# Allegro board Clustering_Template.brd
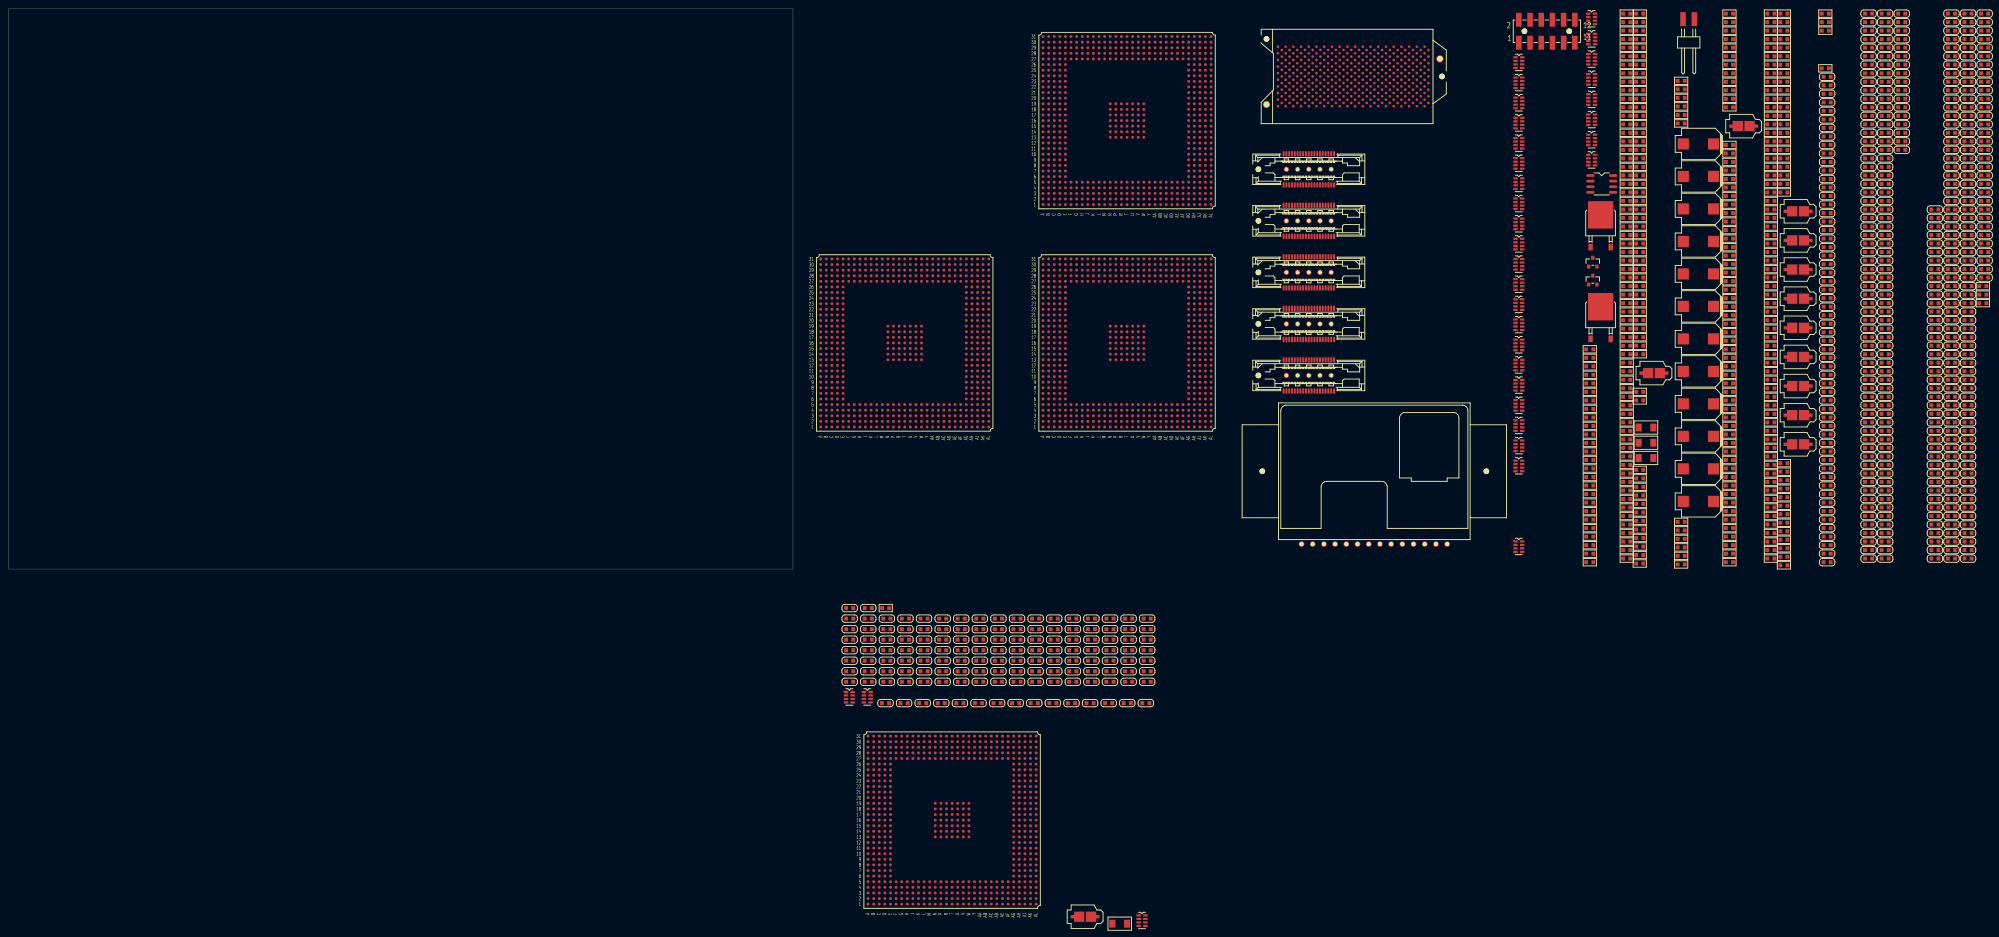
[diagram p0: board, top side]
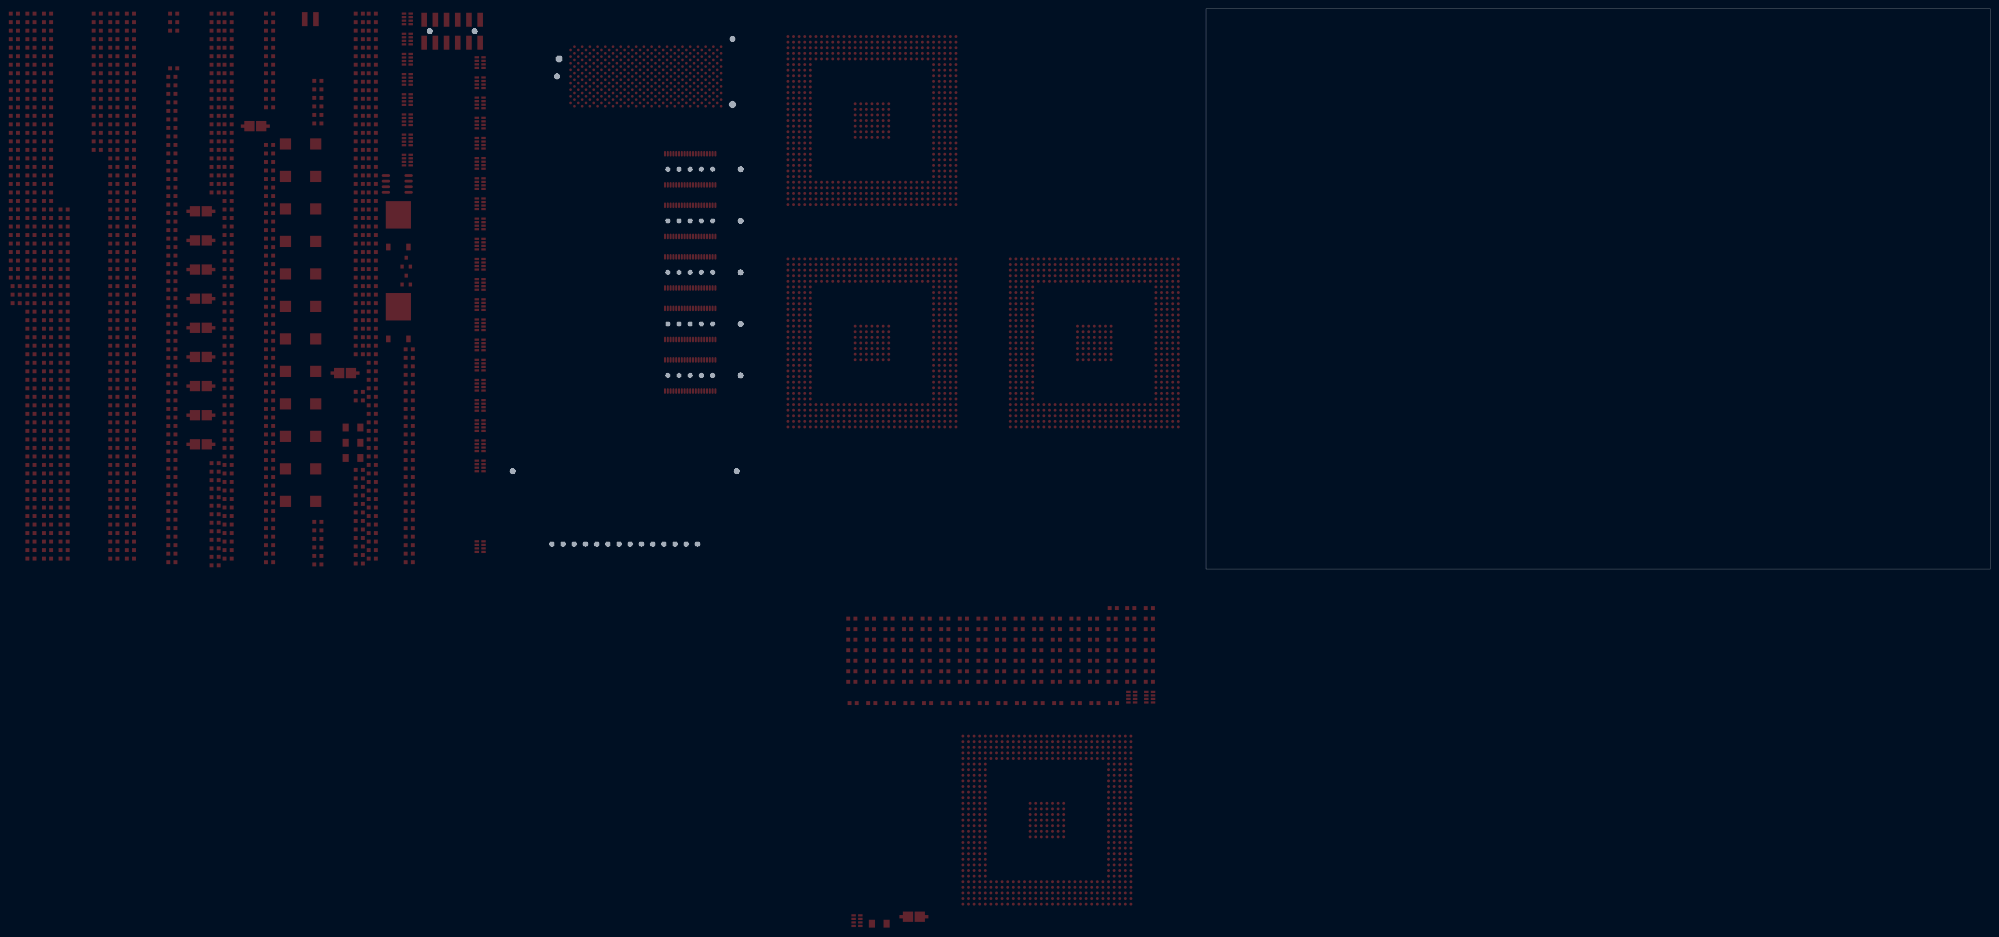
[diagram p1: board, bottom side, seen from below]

Outline 177.8 x 127 mm; copper layers: TOP, INNER1, INNER2, INNER3, INNER4, BOTTOM. Coordinates in mm from the lower left corner of the outline.
Outline path: 0,127 0,0 177.8,0 177.8,127 0,127

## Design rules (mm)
constraint set DEFAULT: min track width 0.114
net group PWR_NET: nets 3.3V GND

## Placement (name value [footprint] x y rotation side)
C1  470PF_50V  [RC0603_1]  399.53 25.53 0 top
C2  470PF_50V  [RC0603_1]  399.53 27.46 0 top
C3  470PF_50V  [RC0603_1]  399.53 29.39 0 top
C4  470PF_50V  [RC0603_1]  399.53 31.32 0 top
C5  470PF_50V  [RC0603_1]  399.53 33.25 0 top
C6  470PF_50V  [RC0603_1]  399.53 35.18 0 top
C7  470PF_50V  [RC0603_1]  399.53 37.11 0 top
C8  470PF_50V  [RC0603_1]  399.53 39.04 0 top
C9  470PF_50V  [RC0603_1]  399.53 40.97 0 top
C10  470PF_50V  [RC0603_1]  399.53 42.9 0 top
C11  470PF_50V  [RC0603_1]  399.53 44.83 0 top
C12  470PF_50V  [RC0603_1]  399.53 46.76 0 top
C13  470PF_50V  [RC0603_1]  399.53 48.69 0 top
C14  470PF_50V  [RC0603_1]  399.53 50.62 0 top
C15  470PF_50V  [RC0603_1]  399.53 52.55 0 top
C16  470PF_50V  [RC0603_1]  399.53 54.48 0 top
C17  470PF_50V  [RC0603_1]  399.53 56.41 0 top
C18  470PF_50V  [RC0603_1]  399.53 58.34 0 top
C19  470PF_50V  [RC0603_1]  399.53 60.27 0 top
C20  470PF_50V  [RC0603_1]  399.53 62.2 0 top
C21  470PF_50V  [RC0603_1]  399.53 64.14 0 top
C22  470PF_50V  [RC0603_1]  399.53 66.07 0 top
C23  470PF_50V  [RC0603_1]  399.53 68 0 top
C24  470PF_50V  [RC0603_1]  399.53 69.93 0 top
C25  470PF_50V  [RC0603_1]  399.53 71.86 0 top
C26  470PF_50V  [RC0603_1]  399.53 73.79 0 top
C27  470PF_50V  [RC0603_1]  399.53 75.72 0 top
C28  470PF_50V  [RC0603_1]  399.53 77.65 0 top
C29  470PF_50V  [RC0603_1]  399.53 79.58 0 top
C30  470PF_50V  [RC0603_1]  399.53 81.51 0 top
C31  470PF_50V  [RC0603_1]  399.53 83.44 0 top
C32  470PF_50V  [RC0603_1]  399.53 85.37 0 top
C33  470PF_50V  [RC0603_1]  399.53 87.3 0 top
C34  470PF_50V  [RC0603_1]  399.53 89.23 0 top
C35  470PF_50V  [RC0603_1]  399.53 91.16 0 top
C36  470PF_50V  [RC0603_1]  399.53 93.09 0 top
C37  470PF_50V  [RC0603_1]  399.53 95.02 0 top
C38  470PF_50V  [RC0603_1]  399.53 96.95 0 top
C39  470PF_50V  [RC0603_1]  399.53 98.88 0 top
C40  470PF_50V  [RC0603_1]  399.53 100.81 0 top
C41  470PF_50V  [RC0603_1]  399.53 102.74 0 top
C42  470PF_50V  [RC0603_1]  399.53 104.67 0 top
C43  470PF_50V  [RC0603_1]  399.53 106.6 0 top
C44  470PF_50V  [RC0603_1]  399.53 108.53 0 top
C45  470PF_50V  [RC0603_1]  399.53 110.46 0 top
C46  470PF_50V  [RC0603_1]  399.53 112.39 0 top
C47  470PF_50V  [RC0603_1]  399.53 114.33 0 top
C48  470PF_50V  [RC0603_1]  399.53 116.26 0 top
C49  470PF_50V  [RC0603_1]  399.53 118.19 0 top
C50  470PF_50V  [RC0603_1]  399.53 120.12 0 top
C51  470PF_50V  [RC0603_1]  399.53 122.05 0 top
C52  470PF_50V  [RC0603_1]  399.53 123.98 0 top
C53  470PF_50V  [RC0603_1]  399.53 125.91 0 top
C54  470PF_50V  [RC0603_1]  390.13 1.55 0 top
C55  470PF_50V  [RC0603_1]  390.13 3.48 0 top
C56  470PF_50V  [RC0603_1]  390.13 5.41 0 top
C57  470PF_50V  [RC0603_1]  390.13 7.34 0 top
C58  470PF_50V  [RC0603_1]  390.13 9.27 0 top
C59  470PF_50V  [RC0603_1]  390.13 11.2 0 top
C60  470PF_50V  [RC0603_1]  390.13 13.13 0 top
C61  470PF_50V  [RC0603_1]  390.13 15.06 0 top
C62  470PF_50V  [RC0603_1]  390.13 16.99 0 top
C63  470PF_50V  [RC0603_1]  390.13 18.92 0 top
C64  470PF_50V  [RC0603_1]  390.13 20.85 0 top
C65  470PF_50V  [RC0603_1]  390.13 22.78 0 top
C66  470PF_50V  [RC0603_1]  390.13 24.71 0 top
C67  470PF_50V  [RC0603_1]  390.13 26.64 0 top
C68  470PF_50V  [RC0603_1]  390.13 28.57 0 top
C69  470PF_50V  [RC0603_1]  390.13 30.51 0 top
C70  470PF_50V  [RC0603_1]  390.13 32.44 0 top
C71  470PF_50V  [RC0603_1]  390.13 34.37 0 top
C72  470PF_50V  [RC0603_1]  390.13 36.3 0 top
C73  470PF_50V  [RC0603_1]  390.13 38.23 0 top
C74  470PF_50V  [RC0603_1]  390.13 40.16 0 top
C75  470PF_50V  [RC0603_1]  390.13 42.09 0 top
C76  470PF_50V  [RC0603_1]  390.13 44.02 0 top
C77  470PF_50V  [RC0603_1]  390.13 45.95 0 top
C78  470PF_50V  [RC0603_1]  390.13 47.88 0 top
C79  470PF_50V  [RC0603_1]  390.13 49.81 0 top
C80  470PF_50V  [RC0603_1]  390.13 51.74 0 top
C81  470PF_50V  [RC0603_1]  390.13 53.67 0 top
C82  470PF_50V  [RC0603_1]  390.13 55.6 0 top
C83  470PF_50V  [RC0603_1]  390.13 57.53 0 top
C84  470PF_50V  [RC0603_1]  390.13 59.46 0 top
C85  470PF_50V  [RC0603_1]  390.13 61.39 0 top
C86  470PF_50V  [RC0603_1]  390.13 63.32 0 top
C87  470PF_50V  [RC0603_1]  390.13 65.25 0 top
C88  470PF_50V  [RC0603_1]  390.13 67.18 0 top
C89  470PF_50V  [RC0603_1]  390.13 69.11 0 top
C90  470PF_50V  [RC0603_1]  390.13 71.04 0 top
C91  470PF_50V  [RC0603_1]  390.13 72.97 0 top
C92  470PF_50V  [RC0603_1]  390.13 74.9 0 top
C93  470PF_50V  [RC0603_1]  390.13 76.83 0 top
C94  470PF_50V  [RC0603_1]  390.13 78.77 0 top
C95  470PF_50V  [RC0603_1]  390.13 80.7 0 top
C96  470PF_50V  [RC0603_1]  390.13 82.63 0 top
C97  470PF_50V  [RC0603_1]  390.13 84.56 0 top
C98  470PF_50V  [RC0603_1]  390.13 86.49 0 top
C99  470PF_50V  [RC0603_1]  390.13 88.42 0 top
C100  470PF_50V  [RC0603_1]  390.13 90.35 0 top
C101  470PF_50V  [RC0603_1]  390.13 92.28 0 top
C102  470PF_50V  [RC0603_1]  390.13 94.21 0 top
C103  470PF_50V  [RC0603_1]  390.13 96.14 0 top
C104  470PF_50V  [RC0603_1]  411.88 113.51 0 top
C105  470PF_50V  [RC0603_1]  390.13 104.67 0 top
C106  470PF_50V  [RC0603_1]  390.13 106.6 0 top
C107  470PF_50V  [RC0603_1]  390.13 108.53 0 top
C108  470PF_50V  [RC0603_1]  390.13 110.46 0 top
C109  470PF_50V  [RC0603_1]  390.13 112.39 0 top
C110  470PF_50V  [RC0603_1]  390.13 114.33 0 top
C111  470PF_50V  [RC0603_1]  390.13 116.26 0 top
C112  470PF_50V  [RC0603_1]  390.13 118.19 0 top
C113  470PF_50V  [RC0603_1]  390.13 120.12 0 top
C114  470PF_50V  [RC0603_1]  390.13 122.05 0 top
C115  470PF_50V  [RC0603_1]  390.13 123.98 0 top
C116  470PF_50V  [RC0603_1]  390.13 125.91 0 top
C117  470PF_50V  [RC0603_1]  379.19 1.04 0 top
C118  470PF_50V  [RC0603_1]  379.19 2.97 0 top
C119  470PF_50V  [RC0603_1]  379.19 4.9 0 top
C120  0.1UF_16V  [BC0603_P1_1]  198.78 -30.39 0 top
C121  0.1UF_16V  [BC0603_P1_1]  203 -30.39 0 top
C122  0.1UF_16V  [BC0603_P1_1]  207.21 -30.39 0 top
C123  0.1UF_16V  [BC0603_P1_1]  211.43 -30.39 0 top
C124  0.1UF_16V  [BC0603_P1_1]  215.65 -30.39 0 top
C125  0.1UF_16V  [BC0603_P1_1]  219.86 -30.39 0 top
C126  0.1UF_16V  [BC0603_P1_1]  224.08 -30.39 0 top
C127  0.1UF_16V  [BC0603_P1_1]  228.3 -30.39 0 top
C128  0.1UF_16V  [BC0603_P1_1]  232.51 -30.39 0 top
C129  0.1UF_16V  [BC0603_P1_1]  236.73 -30.39 0 top
C130  0.1UF_16V  [BC0603_P1_1]  240.94 -30.39 0 top
C131  0.1UF_16V  [BC0603_P1_1]  245.16 -30.39 0 top
C132  0.1UF_16V  [BC0603_P1_1]  249.38 -30.39 0 top
C133  0.1UF_16V  [BC0603_P1_1]  253.59 -30.39 0 top
C134  0.1UF_16V  [BC0603_P1_1]  257.81 -30.39 0 top
C135  0.1UF_16V  [BC0603_P1_1]  190.65 -25.57 0 top
C136  0.1UF_16V  [BC0603_P1_1]  194.87 -25.57 0 top
C137  0.1UF_16V  [BC0603_P1_1]  199.09 -25.57 0 top
C138  0.1UF_16V  [BC0603_P1_1]  203.3 -25.57 0 top
C139  0.1UF_16V  [BC0603_P1_1]  207.52 -25.57 0 top
C140  0.1UF_16V  [BC0603_P1_1]  211.73 -25.57 0 top
C141  0.1UF_16V  [BC0603_P1_1]  215.95 -25.57 0 top
C142  0.1UF_16V  [BC0603_P1_1]  220.17 -25.57 0 top
C143  0.1UF_16V  [BC0603_P1_1]  224.38 -25.57 0 top
C144  0.1UF_16V  [BC0603_P1_1]  228.6 -25.57 0 top
C145  0.1UF_16V  [BC0603_P1_1]  232.82 -25.57 0 top
C146  0.1UF_16V  [BC0603_P1_1]  237.03 -25.57 0 top
C147  0.1UF_16V  [BC0603_P1_1]  241.25 -25.57 0 top
C148  0.1UF_16V  [BC0603_P1_1]  245.47 -25.57 0 top
C149  0.1UF_16V  [BC0603_P1_1]  249.68 -25.57 0 top
C150  0.1UF_16V  [BC0603_P1_1]  253.9 -25.57 0 top
C151  0.1UF_16V  [BC0603_P1_1]  258.11 -25.57 0 top
C152  0.1UF_16V  [BC0603_P1_1]  190.65 -23.18 0 top
C153  0.1UF_16V  [BC0603_P1_1]  194.87 -23.18 0 top
C154  0.1UF_16V  [BC0603_P1_1]  199.09 -23.18 0 top
C155  0.1UF_16V  [BC0603_P1_1]  203.3 -23.18 0 top
C156  0.1UF_16V  [BC0603_P1_1]  207.52 -23.18 0 top
C157  0.1UF_16V  [BC0603_P1_1]  211.73 -23.18 0 top
C158  0.1UF_16V  [BC0603_P1_1]  215.95 -23.18 0 top
C159  0.1UF_16V  [BC0603_P1_1]  220.17 -23.18 0 top
C160  0.1UF_16V  [BC0603_P1_1]  224.38 -23.18 0 top
C161  0.1UF_16V  [BC0603_P1_1]  228.6 -23.18 0 top
C162  0.1UF_16V  [BC0603_P1_1]  232.82 -23.18 0 top
C163  0.1UF_16V  [BC0603_P1_1]  237.03 -23.18 0 top
C164  0.1UF_16V  [BC0603_P1_1]  241.25 -23.18 0 top
C165  0.1UF_16V  [BC0603_P1_1]  245.47 -23.18 0 top
C166  0.1UF_16V  [BC0603_P1_1]  249.68 -23.18 0 top
C167  0.1UF_16V  [BC0603_P1_1]  253.9 -23.18 0 top
C168  0.1UF_16V  [BC0603_P1_1]  258.11 -23.18 0 top
C169  0.1UF_16V  [BC0603_P1_1]  190.65 -20.79 0 top
C170  0.1UF_16V  [BC0603_P1_1]  194.87 -20.79 0 top
C171  0.1UF_16V  [BC0603_P1_1]  199.09 -20.79 0 top
C172  0.1UF_16V  [BC0603_P1_1]  203.3 -20.79 0 top
C173  0.1UF_16V  [BC0603_P1_1]  207.52 -20.79 0 top
C174  0.1UF_16V  [BC0603_P1_1]  211.73 -20.79 0 top
C175  0.1UF_16V  [BC0603_P1_1]  215.95 -20.79 0 top
C176  0.1UF_16V  [BC0603_P1_1]  220.17 -20.79 0 top
C177  0.1UF_16V  [BC0603_P1_1]  224.38 -20.79 0 top
C178  0.1UF_16V  [BC0603_P1_1]  228.6 -20.79 0 top
C179  0.1UF_16V  [BC0603_P1_1]  232.82 -20.79 0 top
C180  0.1UF_16V  [BC0603_P1_1]  237.03 -20.79 0 top
C181  0.1UF_16V  [BC0603_P1_1]  241.25 -20.79 0 top
C182  0.1UF_16V  [BC0603_P1_1]  245.47 -20.79 0 top
C183  0.1UF_16V  [BC0603_P1_1]  249.68 -20.79 0 top
C184  0.1UF_16V  [BC0603_P1_1]  253.9 -20.79 0 top
C185  0.1UF_16V  [BC0603_P1_1]  258.11 -20.79 0 top
C186  0.1UF_16V  [BC0603_P1_1]  190.65 -18.4 0 top
C187  0.1UF_16V  [BC0603_P1_1]  194.87 -18.4 0 top
C188  0.1UF_16V  [BC0603_P1_1]  199.09 -18.4 0 top
C189  0.1UF_16V  [BC0603_P1_1]  203.3 -18.4 0 top
C190  0.1UF_16V  [BC0603_P1_1]  207.52 -18.4 0 top
C191  0.1UF_16V  [BC0603_P1_1]  211.73 -18.4 0 top
C192  0.1UF_16V  [BC0603_P1_1]  215.95 -18.4 0 top
C193  0.1UF_16V  [BC0603_P1_1]  220.17 -18.4 0 top
C194  0.1UF_16V  [BC0603_P1_1]  224.38 -18.4 0 top
C195  0.1UF_16V  [BC0603_P1_1]  228.6 -18.4 0 top
C196  0.1UF_16V  [BC0603_P1_1]  232.82 -18.4 0 top
C197  0.1UF_16V  [BC0603_P1_1]  237.03 -18.4 0 top
C198  0.1UF_16V  [BC0603_P1_1]  241.25 -18.4 0 top
C199  0.1UF_16V  [BC0603_P1_1]  245.47 -18.4 0 top
C200  0.1UF_16V  [BC0603_P1_1]  249.68 -18.4 0 top
C201  0.1UF_16V  [BC0603_P1_1]  253.9 -18.4 0 top
C202  0.1UF_16V  [BC0603_P1_1]  258.11 -18.4 0 top
C203  0.1UF_16V  [BC0603_P1_1]  190.65 -16.02 0 top
C204  0.1UF_16V  [BC0603_P1_1]  194.87 -16.02 0 top
C205  0.1UF_16V  [BC0603_P1_1]  199.09 -16.02 0 top
C206  0.1UF_16V  [BC0603_P1_1]  203.3 -16.02 0 top
C207  0.1UF_16V  [BC0603_P1_1]  207.52 -16.02 0 top
C208  0.1UF_16V  [BC0603_P1_1]  211.73 -16.02 0 top
C209  0.1UF_16V  [BC0603_P1_1]  215.95 -16.02 0 top
C210  0.1UF_16V  [BC0603_P1_1]  220.17 -16.02 0 top
C211  0.1UF_16V  [BC0603_P1_1]  224.38 -16.02 0 top
C212  0.1UF_16V  [BC0603_P1_1]  228.6 -16.02 0 top
C213  0.1UF_16V  [BC0603_P1_1]  232.82 -16.02 0 top
C214  0.1UF_16V  [BC0603_P1_1]  237.03 -16.02 0 top
C215  0.1UF_16V  [BC0603_P1_1]  241.25 -16.02 0 top
C216  0.1UF_16V  [BC0603_P1_1]  245.47 -16.02 0 top
C217  0.1UF_16V  [BC0603_P1_1]  249.68 -16.02 0 top
C218  0.1UF_16V  [BC0603_P1_1]  253.9 -16.02 0 top
C219  0.1UF_16V  [BC0603_P1_1]  258.11 -16.02 0 top
C220  0.1UF_16V  [BC0603_P1_1]  190.65 -13.63 0 top
C221  0.1UF_16V  [BC0603_P1_1]  194.87 -13.63 0 top
C222  0.1UF_16V  [BC0603_P1_1]  199.09 -13.63 0 top
C223  0.1UF_16V  [BC0603_P1_1]  203.3 -13.63 0 top
C224  0.1UF_16V  [BC0603_P1_1]  207.52 -13.63 0 top
C225  0.1UF_16V  [BC0603_P1_1]  211.73 -13.63 0 top
C226  0.1UF_16V  [BC0603_P1_1]  215.95 -13.63 0 top
C227  0.1UF_16V  [BC0603_P1_1]  220.17 -13.63 0 top
C228  0.1UF_16V  [BC0603_P1_1]  224.38 -13.63 0 top
C229  0.1UF_16V  [BC0603_P1_1]  228.6 -13.63 0 top
C230  0.1UF_16V  [BC0603_P1_1]  232.82 -13.63 0 top
C231  0.1UF_16V  [BC0603_P1_1]  237.03 -13.63 0 top
C232  0.1UF_16V  [BC0603_P1_1]  241.25 -13.63 0 top
C233  0.1UF_16V  [BC0603_P1_1]  245.47 -13.63 0 top
C234  0.1UF_16V  [BC0603_P1_1]  249.68 -13.63 0 top
C235  0.1UF_16V  [BC0603_P1_1]  253.9 -13.63 0 top
C236  0.1UF_16V  [BC0603_P1_1]  258.11 -13.63 0 top
C237  0.1UF_16V  [BC0603_P1_1]  190.65 -11.24 0 top
C238  0.1UF_16V  [BC0603_P1_1]  194.87 -11.24 0 top
C239  0.1UF_16V  [BC0603_P1_1]  199.09 -11.24 0 top
C240  0.1UF_16V  [BC0603_P1_1]  203.3 -11.24 0 top
C241  0.1UF_16V  [BC0603_P1_1]  207.52 -11.24 0 top
C242  0.1UF_16V  [BC0603_P1_1]  211.73 -11.24 0 top
C243  0.1UF_16V  [BC0603_P1_1]  215.95 -11.24 0 top
C244  0.1UF_16V  [BC0603_P1_1]  220.17 -11.24 0 top
C245  0.1UF_16V  [BC0603_P1_1]  224.38 -11.24 0 top
C246  0.1UF_16V  [BC0603_P1_1]  228.6 -11.24 0 top
C247  0.1UF_16V  [BC0603_P1_1]  232.82 -11.24 0 top
C248  0.1UF_16V  [BC0603_P1_1]  237.03 -11.24 0 top
C249  0.1UF_16V  [BC0603_P1_1]  241.25 -11.24 0 top
C250  0.1UF_16V  [BC0603_P1_1]  245.47 -11.24 0 top
C251  0.1UF_16V  [BC0603_P1_1]  249.68 -11.24 0 top
C252  0.1UF_16V  [BC0603_P1_1]  253.9 -11.24 0 top
C253  0.1UF_16V  [BC0603_P1_1]  258.11 -11.24 0 top
C254  0.1UF_16V  [BC0603_P1_1]  190.65 -8.85 0 top
C255  0.1UF_16V  [BC0603_P1_1]  194.87 -8.85 0 top
C256  0.1UF_16V  [BC0603_P1_1]  429.2 95.02 0 top
C257  0.1UF_16V  [BC0603_P1_1]  429.2 96.95 0 top
C258  0.1UF_16V  [BC0603_P1_1]  429.2 98.88 0 top
C259  0.1UF_16V  [BC0603_P1_1]  429.2 100.81 0 top
C260  0.1UF_16V  [BC0603_P1_1]  429.2 102.74 0 top
C261  0.1UF_16V  [BC0603_P1_1]  429.2 104.67 0 top
C262  0.1UF_16V  [BC0603_P1_1]  429.2 106.6 0 top
C263  0.1UF_16V  [BC0603_P1_1]  429.2 108.53 0 top
C264  0.1UF_16V  [BC0603_P1_1]  429.2 110.46 0 top
C265  0.1UF_16V  [BC0603_P1_1]  429.2 112.39 0 top
C266  0.1UF_16V  [BC0603_P1_1]  429.2 114.33 0 top
C267  0.1UF_16V  [BC0603_P1_1]  429.2 116.26 0 top
C268  0.1UF_16V  [BC0603_P1_1]  429.2 118.19 0 top
C269  0.1UF_16V  [BC0603_P1_1]  429.2 120.12 0 top
C270  0.1UF_16V  [BC0603_P1_1]  429.2 122.05 0 top
C271  0.1UF_16V  [BC0603_P1_1]  429.2 123.98 0 top
C272  0.1UF_16V  [BC0603_P1_1]  429.2 125.91 0 top
C273  0.1UF_16V  [BC0603_P1_1]  425.44 2.36 0 top
C274  0.1UF_16V  [BC0603_P1_1]  425.44 4.29 0 top
C275  0.1UF_16V  [BC0603_P1_1]  448 66.07 0 top
C276  0.1UF_16V  [BC0603_P1_1]  448 68 0 top
C277  0.1UF_16V  [BC0603_P1_1]  448 69.93 0 top
C278  0.1UF_16V  [BC0603_P1_1]  448 71.86 0 top
C279  0.1UF_16V  [BC0603_P1_1]  448 73.79 0 top
C280  0.1UF_16V  [BC0603_P1_1]  448 75.72 0 top
C281  0.1UF_16V  [BC0603_P1_1]  448 77.65 0 top
C282  0.1UF_16V  [BC0603_P1_1]  448 79.58 0 top
C283  0.1UF_16V  [BC0603_P1_1]  448 81.51 0 top
C284  0.1UF_16V  [BC0603_P1_1]  448 83.44 0 top
C285  0.1UF_16V  [BC0603_P1_1]  448 85.37 0 top
C286  0.1UF_16V  [BC0603_P1_1]  448 87.3 0 top
C287  0.1UF_16V  [BC0603_P1_1]  448 89.23 0 top
C288  0.1UF_16V  [BC0603_P1_1]  448 91.16 0 top
C289  0.1UF_16V  [BC0603_P1_1]  448 93.09 0 top
C290  0.1UF_16V  [BC0603_P1_1]  448 95.02 0 top
C291  0.1UF_16V  [BC0603_P1_1]  448 96.95 0 top
C292  0.1UF_16V  [BC0603_P1_1]  448 98.88 0 top
C293  0.1UF_16V  [BC0603_P1_1]  448 100.81 0 top
C294  0.1UF_16V  [BC0603_P1_1]  448 102.74 0 top
C295  0.1UF_16V  [BC0603_P1_1]  448 104.67 0 top
C296  0.1UF_16V  [BC0603_P1_1]  448 106.6 0 top
C297  0.1UF_16V  [BC0603_P1_1]  448 108.53 0 top
C298  0.1UF_16V  [BC0603_P1_1]  448 110.46 0 top
C299  0.1UF_16V  [BC0603_P1_1]  448 112.39 0 top
C300  0.1UF_16V  [BC0603_P1_1]  448 114.33 0 top
C301  0.1UF_16V  [BC0603_P1_1]  448 116.26 0 top
C302  0.1UF_16V  [BC0603_P1_1]  448 118.19 0 top
C303  0.1UF_16V  [BC0603_P1_1]  448 120.12 0 top
C304  0.1UF_16V  [BC0603_P1_1]  448 122.05 0 top
C305  0.1UF_16V  [BC0603_P1_1]  448 123.98 0 top
C306  0.1UF_16V  [BC0603_P1_1]  448 125.91 0 top
C307  0.1UF_16V  [BC0603_P1_1]  425.44 6.22 0 top
C308  0.1UF_16V  [BC0603_P1_1]  444.24 2.36 0 top
C309  0.1UF_16V  [BC0603_P1_1]  425.44 8.15 0 top
C310  0.1UF_16V  [BC0603_P1_1]  425.44 10.08 0 top
C311  0.1UF_16V  [BC0603_P1_1]  444.24 4.29 0 top
C312  0.1UF_16V  [BC0603_P1_1]  425.44 12.01 0 top
C313  0.1UF_16V  [BC0603_P1_1]  425.44 13.94 0 top
C314  0.1UF_16V  [BC0603_P1_1]  444.24 6.22 0 top
C315  0.1UF_16V  [BC0603_P1_1]  444.24 8.15 0 top
C316  0.1UF_16V  [BC0603_P1_1]  444.24 10.08 0 top
C317  0.1UF_16V  [BC0603_P1_1]  444.24 12.01 0 top
C318  0.1UF_16V  [BC0603_P1_1]  444.24 13.94 0 top
C319  0.1UF_16V  [BC0603_P1_1]  444.24 15.88 0 top
C320  0.1UF_16V  [BC0603_P1_1]  444.24 17.81 0 top
C321  0.1UF_16V  [BC0603_P1_1]  444.24 19.74 0 top
C322  0.1UF_16V  [BC0603_P1_1]  444.24 21.67 0 top
C323  0.1UF_16V  [BC0603_P1_1]  425.44 15.88 0 top
C324  0.1UF_16V  [BC0603_P1_1]  425.44 17.81 0 top
C325  0.1UF_16V  [BC0603_P1_1]  444.24 23.6 0 top
C326  0.1UF_16V  [BC0603_P1_1]  444.24 25.53 0 top
C327  0.1UF_16V  [BC0603_P1_1]  444.24 27.46 0 top
C328  0.1UF_16V  [BC0603_P1_1]  444.24 29.39 0 top
C329  0.1UF_16V  [BC0603_P1_1]  444.24 31.32 0 top
C330  0.1UF_16V  [BC0603_P1_1]  444.24 33.25 0 top
C331  0.1UF_16V  [BC0603_P1_1]  444.24 35.18 0 top
C332  0.1UF_16V  [BC0603_P1_1]  444.24 37.11 0 top
C333  0.1UF_16V  [BC0603_P1_1]  444.24 39.04 0 top
C334  0.1UF_16V  [BC0603_P1_1]  444.24 40.97 0 top
C335  0.1UF_16V  [BC0603_P1_1]  444.24 42.9 0 top
C336  0.1UF_16V  [BC0603_P1_1]  444.24 44.83 0 top
C337  0.1UF_16V  [BC0603_P1_1]  444.24 46.76 0 top
C338  0.1UF_16V  [BC0603_P1_1]  444.24 48.69 0 top
C339  0.1UF_16V  [BC0603_P1_1]  444.24 50.62 0 top
C340  0.1UF_16V  [BC0603_P1_1]  444.24 52.55 0 top
C341  0.1UF_16V  [BC0603_P1_1]  444.24 54.48 0 top
C342  0.1UF_16V  [BC0603_P1_1]  444.24 56.41 0 top
C343  0.1UF_16V  [BC0603_P1_1]  444.24 58.34 0 top
C344  0.1UF_16V  [BC0603_P1_1]  444.24 60.27 0 top
C345  0.1UF_16V  [BC0603_P1_1]  444.24 62.2 0 top
C346  0.1UF_16V  [BC0603_P1_1]  444.24 64.14 0 top
C347  0.1UF_16V  [BC0603_P1_1]  444.24 66.07 0 top
C348  0.1UF_16V  [BC0603_P1_1]  444.24 68 0 top
C349  0.1UF_16V  [BC0603_P1_1]  444.24 69.93 0 top
C350  0.1UF_16V  [BC0603_P1_1]  444.24 71.86 0 top
C351  0.1UF_16V  [BC0603_P1_1]  444.24 73.79 0 top
C352  0.1UF_16V  [BC0603_P1_1]  444.24 75.72 0 top
C353  0.1UF_16V  [BC0603_P1_1]  444.24 77.65 0 top
C354  0.1UF_16V  [BC0603_P1_1]  444.24 79.58 0 top
C355  0.1UF_16V  [BC0603_P1_1]  444.24 81.51 0 top
C356  0.1UF_16V  [BC0603_P1_1]  444.24 83.44 0 top
C357  0.1UF_16V  [BC0603_P1_1]  444.24 85.37 0 top
C358  0.1UF_16V  [BC0603_P1_1]  444.24 87.3 0 top
C359  0.1UF_16V  [BC0603_P1_1]  444.24 89.23 0 top
C360  0.1UF_16V  [BC0603_P1_1]  444.24 91.16 0 top
C361  0.1UF_16V  [BC0603_P1_1]  444.24 93.09 0 top
C362  0.1UF_16V  [BC0603_P1_1]  444.24 95.02 0 top
C363  0.1UF_16V  [BC0603_P1_1]  444.24 96.95 0 top
C364  0.1UF_16V  [BC0603_P1_1]  444.24 98.88 0 top
C365  0.1UF_16V  [BC0603_P1_1]  444.24 100.81 0 top
C366  0.1UF_16V  [BC0603_P1_1]  444.24 102.74 0 top
C367  0.1UF_16V  [BC0603_P1_1]  444.24 104.67 0 top
C368  0.1UF_16V  [BC0603_P1_1]  444.24 106.6 0 top
C369  0.1UF_16V  [BC0603_P1_1]  444.24 108.53 0 top
C370  0.1UF_16V  [BC0603_P1_1]  444.24 110.46 0 top
C371  0.1UF_16V  [BC0603_P1_1]  444.24 112.39 0 top
C372  0.1UF_16V  [BC0603_P1_1]  444.24 114.33 0 top
C373  0.1UF_16V  [BC0603_P1_1]  444.24 116.26 0 top
C374  0.1UF_16V  [BC0603_P1_1]  444.24 118.19 0 top
C375  0.1UF_16V  [BC0603_P1_1]  444.24 120.12 0 top
C376  0.1UF_16V  [BC0603_P1_1]  444.24 122.05 0 top
C377  0.1UF_16V  [BC0603_P1_1]  444.24 123.98 0 top
C378  0.1UF_16V  [BC0603_P1_1]  444.24 125.91 0 top
C379  0.1UF_16V  [BC0603_P1_1]  440.48 2.36 0 top
C380  0.1UF_16V  [BC0603_P1_1]  440.48 4.29 0 top
C381  0.1UF_16V  [BC0603_P1_1]  440.48 6.22 0 top
C382  0.1UF_16V  [BC0603_P1_1]  440.48 8.15 0 top
C383  0.1UF_16V  [BC0603_P1_1]  440.48 10.08 0 top
C384  0.1UF_16V  [BC0603_P1_1]  440.48 12.01 0 top
C385  0.1UF_16V  [BC0603_P1_1]  440.48 13.94 0 top
C386  0.1UF_16V  [BC0603_P1_1]  440.48 15.88 0 top
C387  0.1UF_16V  [BC0603_P1_1]  440.48 17.81 0 top
C388  0.1UF_16V  [BC0603_P1_1]  440.48 19.74 0 top
C389  0.1UF_16V  [BC0603_P1_1]  440.48 21.67 0 top
C390  0.1UF_16V  [BC0603_P1_1]  440.48 23.6 0 top
C391  0.1UF_16V  [BC0603_P1_1]  440.48 25.53 0 top
C392  0.1UF_16V  [BC0603_P1_1]  440.48 27.46 0 top
C393  0.1UF_16V  [BC0603_P1_1]  440.48 29.39 0 top
C394  0.1UF_16V  [BC0603_P1_1]  440.48 31.32 0 top
C395  0.1UF_16V  [BC0603_P1_1]  440.48 33.25 0 top
C396  0.1UF_16V  [BC0603_P1_1]  440.48 35.18 0 top
C397  0.1UF_16V  [BC0603_P1_1]  440.48 37.11 0 top
C398  0.1UF_16V  [BC0603_P1_1]  440.48 39.04 0 top
C399  0.1UF_16V  [BC0603_P1_1]  440.48 40.97 0 top
C400  0.1UF_16V  [BC0603_P1_1]  440.48 42.9 0 top
C401  0.1UF_16V  [BC0603_P1_1]  440.48 44.83 0 top
C402  0.1UF_16V  [BC0603_P1_1]  440.48 46.76 0 top
C403  0.1UF_16V  [BC0603_P1_1]  440.48 48.69 0 top
C404  0.1UF_16V  [BC0603_P1_1]  425.44 19.74 0 top
C405  0.1UF_16V  [BC0603_P1_1]  425.44 21.67 0 top
C406  0.1UF_16V  [BC0603_P1_1]  425.44 23.6 0 top
C407  0.1UF_16V  [BC0603_P1_1]  425.44 25.53 0 top
C408  0.1UF_16V  [BC0603_P1_1]  425.44 27.46 0 top
C409  0.1UF_16V  [BC0603_P1_1]  425.44 29.39 0 top
C410  0.1UF_16V  [BC0603_P1_1]  425.44 31.32 0 top
C411  0.1UF_16V  [BC0603_P1_1]  440.48 50.62 0 top
C412  0.1UF_16V  [BC0603_P1_1]  440.48 52.55 0 top
C413  0.1UF_16V  [BC0603_P1_1]  440.48 54.48 0 top
C414  0.1UF_16V  [BC0603_P1_1]  440.48 56.41 0 top
C415  0.1UF_16V  [BC0603_P1_1]  440.48 58.34 0 top
C416  0.1UF_16V  [BC0603_P1_1]  440.48 60.27 0 top
C417  0.1UF_16V  [BC0603_P1_1]  440.48 62.2 0 top
C418  0.1UF_16V  [BC0603_P1_1]  440.48 64.14 0 top
C419  0.1UF_16V  [BC0603_P1_1]  440.48 66.07 0 top
C420  0.1UF_16V  [BC0603_P1_1]  440.48 68 0 top
C421  0.1UF_16V  [BC0603_P1_1]  440.48 69.93 0 top
C422  0.1UF_16V  [BC0603_P1_1]  440.48 71.86 0 top
C423  0.1UF_16V  [BC0603_P1_1]  440.48 73.79 0 top
C424  0.1UF_16V  [BC0603_P1_1]  440.48 75.72 0 top
C425  0.1UF_16V  [BC0603_P1_1]  425.44 33.25 0 top
C426  0.1UF_16V  [BC0603_P1_1]  425.44 35.18 0 top
C427  0.1UF_16V  [BC0603_P1_1]  425.44 37.11 0 top
C428  0.1UF_16V  [BC0603_P1_1]  425.44 39.04 0 top
C429  0.1UF_16V  [BC0603_P1_1]  425.44 40.97 0 top
C430  0.1UF_16V  [BC0603_P1_1]  425.44 42.9 0 top
C431  0.1UF_16V  [BC0603_P1_1]  425.44 44.83 0 top
C432  0.1UF_16V  [BC0603_P1_1]  425.44 46.76 0 top
C433  0.1UF_16V  [BC0603_P1_1]  425.44 48.69 0 top
C434  0.1UF_16V  [BC0603_P1_1]  425.44 50.62 0 top
C435  0.1UF_16V  [BC0603_P1_1]  440.48 77.65 0 top
C436  0.1UF_16V  [BC0603_P1_1]  440.48 79.58 0 top
C437  0.1UF_16V  [BC0603_P1_1]  440.48 81.51 0 top
C438  0.1UF_16V  [BC0603_P1_1]  440.48 83.44 0 top
C439  0.1UF_16V  [BC0603_P1_1]  440.48 85.37 0 top
C440  0.1UF_16V  [BC0603_P1_1]  440.48 87.3 0 top
C441  0.1UF_16V  [BC0603_P1_1]  440.48 89.23 0 top
C442  0.1UF_16V  [BC0603_P1_1]  440.48 91.16 0 top
C443  0.1UF_16V  [BC0603_P1_1]  440.48 93.09 0 top
C444  0.1UF_16V  [BC0603_P1_1]  440.48 95.02 0 top
C445  0.1UF_16V  [BC0603_P1_1]  440.48 96.95 0 top
C446  0.1UF_16V  [BC0603_P1_1]  440.48 98.88 0 top
C447  0.1UF_16V  [BC0603_P1_1]  440.48 100.81 0 top
C448  0.1UF_16V  [BC0603_P1_1]  440.48 102.74 0 top
C449  0.1UF_16V  [BC0603_P1_1]  440.48 104.67 0 top
C450  0.1UF_16V  [BC0603_P1_1]  440.48 106.6 0 top
C451  0.1UF_16V  [BC0603_P1_1]  440.48 108.53 0 top
C452  0.1UF_16V  [BC0603_P1_1]  440.48 110.46 0 top
C453  0.1UF_16V  [BC0603_P1_1]  440.48 112.39 0 top
C454  0.1UF_16V  [BC0603_P1_1]  440.48 114.33 0 top
C455  0.1UF_16V  [BC0603_P1_1]  440.48 116.26 0 top
C456  0.1UF_16V  [BC0603_P1_1]  440.48 118.19 0 top
C457  0.1UF_16V  [BC0603_P1_1]  440.48 120.12 0 top
C458  0.1UF_16V  [BC0603_P1_1]  440.48 122.05 0 top
C459  0.1UF_16V  [BC0603_P1_1]  440.48 123.98 0 top
C460  0.1UF_16V  [BC0603_P1_1]  440.48 125.91 0 top
C461  0.1UF_16V  [BC0603_P1_1]  436.72 2.36 0 top
C462  0.1UF_16V  [BC0603_P1_1]  436.72 4.29 0 top
C463  0.1UF_16V  [BC0603_P1_1]  436.72 6.22 0 top
C464  0.1UF_16V  [BC0603_P1_1]  436.72 8.15 0 top
C465  0.1UF_16V  [BC0603_P1_1]  436.72 10.08 0 top
C466  0.1UF_16V  [BC0603_P1_1]  436.72 12.01 0 top
C467  0.1UF_16V  [BC0603_P1_1]  436.72 13.94 0 top
C468  0.1UF_16V  [BC0603_P1_1]  436.72 15.88 0 top
C469  0.1UF_16V  [BC0603_P1_1]  436.72 17.81 0 top
C470  0.1UF_16V  [BC0603_P1_1]  436.72 19.74 0 top
C471  0.1UF_16V  [BC0603_P1_1]  436.72 21.67 0 top
C472  0.1UF_16V  [BC0603_P1_1]  436.72 23.6 0 top
C473  0.1UF_16V  [BC0603_P1_1]  436.72 25.53 0 top
C474  0.1UF_16V  [BC0603_P1_1]  436.72 27.46 0 top
C475  0.1UF_16V  [BC0603_P1_1]  436.72 29.39 0 top
C476  0.1UF_16V  [BC0603_P1_1]  436.72 31.32 0 top
C477  0.1UF_16V  [BC0603_P1_1]  436.72 33.25 0 top
C478  0.1UF_16V  [BC0603_P1_1]  436.72 35.18 0 top
C479  0.1UF_16V  [BC0603_P1_1]  436.72 37.11 0 top
C480  0.1UF_16V  [BC0603_P1_1]  436.72 39.04 0 top
C481  0.1UF_16V  [BC0603_P1_1]  436.72 40.97 0 top
C482  0.1UF_16V  [BC0603_P1_1]  436.72 42.9 0 top
C483  0.1UF_16V  [BC0603_P1_1]  436.72 44.83 0 top
C484  0.1UF_16V  [BC0603_P1_1]  436.72 46.76 0 top
C485  0.1UF_16V  [BC0603_P1_1]  436.72 48.69 0 top
C486  0.1UF_16V  [BC0603_P1_1]  436.72 50.62 0 top
C487  0.1UF_16V  [BC0603_P1_1]  436.72 52.55 0 top
C488  0.1UF_16V  [BC0603_P1_1]  436.72 54.48 0 top
C489  0.1UF_16V  [BC0603_P1_1]  436.72 56.41 0 top
C490  0.1UF_16V  [BC0603_P1_1]  436.72 58.34 0 top
C491  0.1UF_16V  [BC0603_P1_1]  436.72 60.27 0 top
C492  0.1UF_16V  [BC0603_P1_1]  436.72 62.2 0 top
C493  0.1UF_16V  [BC0603_P1_1]  436.72 64.14 0 top
C494  0.1UF_16V  [BC0603_P1_1]  436.72 66.07 0 top
C495  0.1UF_16V  [BC0603_P1_1]  436.72 68 0 top
C496  0.1UF_16V  [BC0603_P1_1]  436.72 69.93 0 top
C497  0.1UF_16V  [BC0603_P1_1]  436.72 71.86 0 top
C498  0.1UF_16V  [BC0603_P1_1]  436.72 73.79 0 top
C499  0.1UF_16V  [BC0603_P1_1]  436.72 75.72 0 top
C500  0.1UF_16V  [BC0603_P1_1]  436.72 77.65 0 top
C501  0.1UF_16V  [BC0603_P1_1]  425.44 52.55 0 top
C502  0.1UF_16V  [BC0603_P1_1]  425.44 54.48 0 top
C503  0.1UF_16V  [BC0603_P1_1]  425.44 56.41 0 top
C504  0.1UF_16V  [BC0603_P1_1]  425.44 58.34 0 top
C505  0.1UF_16V  [BC0603_P1_1]  425.44 60.27 0 top
C506  0.1UF_16V  [BC0603_P1_1]  425.44 62.2 0 top
C507  0.1UF_16V  [BC0603_P1_1]  425.44 64.14 0 top
C508  0.1UF_16V  [BC0603_P1_1]  425.44 66.07 0 top
C509  0.1UF_16V  [BC0603_P1_1]  425.44 68 0 top
C510  0.1UF_16V  [BC0603_P1_1]  425.44 69.93 0 top
C511  0.1UF_16V  [BC0603_P1_1]  425.44 71.86 0 top
C512  0.1UF_16V  [BC0603_P1_1]  425.44 73.79 0 top
C513  0.1UF_16V  [BC0603_P1_1]  425.44 75.72 0 top
C514  0.1UF_16V  [BC0603_P1_1]  425.44 77.65 0 top
C515  0.1UF_16V  [BC0603_P1_1]  425.44 79.58 0 top
C516  0.1UF_16V  [BC0603_P1_1]  425.44 81.51 0 top
C517  0.1UF_16V  [BC0603_P1_1]  425.44 83.44 0 top
C518  0.1UF_16V  [BC0603_P1_1]  425.44 85.37 0 top
C519  0.1UF_16V  [BC0603_P1_1]  425.44 87.3 0 top
C520  0.1UF_16V  [BC0603_P1_1]  425.44 89.23 0 top
C521  0.1UF_16V  [BC0603_P1_1]  425.44 91.16 0 top
C522  0.1UF_16V  [BC0603_P1_1]  425.44 93.09 0 top
C523  0.1UF_16V  [BC0603_P1_1]  425.44 95.02 0 top
C524  0.1UF_16V  [BC0603_P1_1]  425.44 96.95 0 top
C525  0.1UF_16V  [BC0603_P1_1]  425.44 98.88 0 top
C526  0.1UF_16V  [BC0603_P1_1]  425.44 100.81 0 top
C527  0.1UF_16V  [BC0603_P1_1]  425.44 102.74 0 top
C528  0.1UF_16V  [BC0603_P1_1]  425.44 104.67 0 top
C529  0.1UF_16V  [BC0603_P1_1]  425.44 106.6 0 top
C530  0.1UF_16V  [BC0603_P1_1]  425.44 108.53 0 top
C531  0.1UF_16V  [BC0603_P1_1]  425.44 110.46 0 top
C532  0.1UF_16V  [BC0603_P1_1]  425.44 112.39 0 top
C533  0.1UF_16V  [BC0603_P1_1]  425.44 114.33 0 top
C534  0.1UF_16V  [BC0603_P1_1]  425.44 116.26 0 top
C535  0.1UF_16V  [BC0603_P1_1]  425.44 118.19 0 top
C536  0.1UF_16V  [BC0603_P1_1]  425.44 120.12 0 top
C537  0.1UF_16V  [BC0603_P1_1]  425.44 122.05 0 top
C538  0.1UF_16V  [BC0603_P1_1]  425.44 123.98 0 top
C539  0.1UF_16V  [BC0603_P1_1]  425.44 125.91 0 top
C540  0.1UF_16V  [BC0603_P1_1]  421.68 2.36 0 top
C541  0.1UF_16V  [BC0603_P1_1]  421.68 4.29 0 top
C542  0.1UF_16V  [BC0603_P1_1]  421.68 6.22 0 top
C543  0.1UF_16V  [BC0603_P1_1]  421.68 8.15 0 top
C544  0.1UF_16V  [BC0603_P1_1]  421.68 10.08 0 top
C545  0.1UF_16V  [BC0603_P1_1]  421.68 12.01 0 top
C546  0.1UF_16V  [BC0603_P1_1]  421.68 13.94 0 top
C547  0.1UF_16V  [BC0603_P1_1]  421.68 15.88 0 top
C548  0.1UF_16V  [BC0603_P1_1]  421.68 17.81 0 top
C549  0.1UF_16V  [BC0603_P1_1]  421.68 19.74 0 top
C550  0.1UF_16V  [BC0603_P1_1]  421.68 21.67 0 top
C551  0.1UF_16V  [BC0603_P1_1]  421.68 23.6 0 top
C552  0.1UF_16V  [BC0603_P1_1]  421.68 25.53 0 top
C553  0.1UF_16V  [BC0603_P1_1]  421.68 27.46 0 top
C554  0.1UF_16V  [BC0603_P1_1]  421.68 29.39 0 top
C555  0.1UF_16V  [BC0603_P1_1]  421.68 31.32 0 top
C556  0.1UF_16V  [BC0603_P1_1]  421.68 33.25 0 top
C557  0.1UF_16V  [BC0603_P1_1]  421.68 35.18 0 top
C558  0.1UF_16V  [BC0603_P1_1]  421.68 37.11 0 top
C559  0.1UF_16V  [BC0603_P1_1]  421.68 39.04 0 top
C560  0.1UF_16V  [BC0603_P1_1]  421.68 40.97 0 top
C561  0.1UF_16V  [BC0603_P1_1]  421.68 42.9 0 top
C562  0.1UF_16V  [BC0603_P1_1]  421.68 44.83 0 top
C563  0.1UF_16V  [BC0603_P1_1]  421.68 46.76 0 top
C564  0.1UF_16V  [BC0603_P1_1]  421.68 48.69 0 top
C565  0.1UF_16V  [BC0603_P1_1]  421.68 50.62 0 top
C566  0.1UF_16V  [BC0603_P1_1]  421.68 52.55 0 top
C567  0.1UF_16V  [BC0603_P1_1]  421.68 54.48 0 top
C568  0.1UF_16V  [BC0603_P1_1]  421.68 56.41 0 top
C569  0.1UF_16V  [BC0603_P1_1]  421.68 58.34 0 top
C570  0.1UF_16V  [BC0603_P1_1]  421.68 60.27 0 top
C571  0.1UF_16V  [BC0603_P1_1]  421.68 62.2 0 top
C572  0.1UF_16V  [BC0603_P1_1]  421.68 64.14 0 top
C573  0.1UF_16V  [BC0603_P1_1]  421.68 66.07 0 top
C574  0.1UF_16V  [BC0603_P1_1]  421.68 68 0 top
C575  0.1UF_16V  [BC0603_P1_1]  421.68 69.93 0 top
C576  0.1UF_16V  [BC0603_P1_1]  421.68 71.86 0 top
C577  0.1UF_16V  [BC0603_P1_1]  421.68 73.79 0 top
C578  0.1UF_16V  [BC0603_P1_1]  421.68 75.72 0 top
C579  0.1UF_16V  [BC0603_P1_1]  436.72 79.58 0 top
C580  0.1UF_16V  [BC0603_P1_1]  436.72 81.51 0 top
C581  0.1UF_16V  [BC0603_P1_1]  421.68 77.65 0 top
C582  0.1UF_16V  [BC0603_P1_1]  421.68 79.58 0 top
C583  0.1UF_16V  [BC0603_P1_1]  421.68 81.51 0 top
C584  0.1UF_16V  [BC0603_P1_1]  421.68 83.44 0 top
C585  0.1UF_16V  [BC0603_P1_1]  421.68 85.37 0 top
C586  0.1UF_16V  [BC0603_P1_1]  421.68 87.3 0 top
C587  0.1UF_16V  [BC0603_P1_1]  421.68 89.23 0 top
C588  0.1UF_16V  [BC0603_P1_1]  421.68 91.16 0 top
C589  0.1UF_16V  [BC0603_P1_1]  421.68 93.09 0 top
C590  0.1UF_16V  [BC0603_P1_1]  421.68 95.02 0 top
C591  0.1UF_16V  [BC0603_P1_1]  421.68 96.95 0 top
C592  0.1UF_16V  [BC0603_P1_1]  421.68 98.88 0 top
C593  0.1UF_16V  [BC0603_P1_1]  421.68 100.81 0 top
C594  0.1UF_16V  [BC0603_P1_1]  421.68 102.74 0 top
C595  0.1UF_16V  [BC0603_P1_1]  421.68 104.67 0 top
C596  0.1UF_16V  [BC0603_P1_1]  421.68 106.6 0 top
C597  0.1UF_16V  [BC0603_P1_1]  421.68 108.53 0 top
C598  0.1UF_16V  [BC0603_P1_1]  421.68 110.46 0 top
C599  0.1UF_16V  [BC0603_P1_1]  421.68 112.39 0 top
C600  0.1UF_16V  [BC0603_P1_1]  421.68 114.33 0 top
C601  0.1UF_16V  [BC0603_P1_1]  421.68 116.26 0 top
C602  0.1UF_16V  [BC0603_P1_1]  421.68 118.19 0 top
C603  0.1UF_16V  [BC0603_P1_1]  421.68 120.12 0 top
C604  0.1UF_16V  [BC0603_P1_1]  421.68 122.05 0 top
C605  0.1UF_16V  [BC0603_P1_1]  421.68 123.98 0 top
C606  0.1UF_16V  [BC0603_P1_1]  421.68 125.91 0 top
C607  0.1UF_16V  [BC0603_P1_1]  412.28 1.55 0 top
C608  0.1UF_16V  [BC0603_P1_1]  412.28 3.48 0 top
C609  0.1UF_16V  [BC0603_P1_1]  412.28 5.41 0 top
C610  0.1UF_16V  [BC0603_P1_1]  412.28 7.34 0 top
C611  0.1UF_16V  [BC0603_P1_1]  412.28 9.27 0 top
C612  0.1UF_16V  [BC0603_P1_1]  412.28 11.2 0 top
C613  0.1UF_16V  [BC0603_P1_1]  412.28 13.13 0 top
C614  0.1UF_16V  [BC0603_P1_1]  412.28 15.06 0 top
C615  0.1UF_16V  [BC0603_P1_1]  412.28 16.99 0 top
C616  0.1UF_16V  [BC0603_P1_1]  412.28 18.92 0 top
C617  0.1UF_16V  [BC0603_P1_1]  412.28 20.85 0 top
C618  0.1UF_16V  [BC0603_P1_1]  412.28 22.78 0 top
C619  0.1UF_16V  [BC0603_P1_1]  412.28 24.71 0 top
C620  0.1UF_16V  [BC0603_P1_1]  412.28 26.64 0 top
C621  0.1UF_16V  [BC0603_P1_1]  412.28 28.57 0 top
C622  0.1UF_16V  [BC0603_P1_1]  412.28 30.51 0 top
C623  0.1UF_16V  [BC0603_P1_1]  412.28 32.44 0 top
C624  0.1UF_16V  [BC0603_P1_1]  412.28 34.37 0 top
C625  0.1UF_16V  [BC0603_P1_1]  412.28 36.3 0 top
C626  0.1UF_16V  [BC0603_P1_1]  412.28 38.23 0 top
C627  0.1UF_16V  [BC0603_P1_1]  412.28 40.16 0 top
C628  0.1UF_16V  [BC0603_P1_1]  412.28 42.09 0 top
C629  0.1UF_16V  [BC0603_P1_1]  412.28 44.02 0 top
C630  0.1UF_16V  [BC0603_P1_1]  412.28 45.95 0 top
C631  0.1UF_16V  [BC0603_P1_1]  412.28 47.88 0 top
C632  0.1UF_16V  [BC0603_P1_1]  412.28 49.81 0 top
C633  0.1UF_16V  [BC0603_P1_1]  412.28 51.74 0 top
C634  0.1UF_16V  [BC0603_P1_1]  412.28 53.67 0 top
C635  0.1UF_16V  [BC0603_P1_1]  412.28 55.6 0 top
C636  0.1UF_16V  [BC0603_P1_1]  412.28 57.53 0 top
C637  0.1UF_16V  [BC0603_P1_1]  412.28 59.46 0 top
C638  0.1UF_16V  [BC0603_P1_1]  412.28 61.39 0 top
C639  0.1UF_16V  [BC0603_P1_1]  412.28 63.32 0 top
C640  0.1UF_16V  [BC0603_P1_1]  412.28 65.25 0 top
C641  0.1UF_16V  [BC0603_P1_1]  412.28 67.18 0 top
C642  0.1UF_16V  [BC0603_P1_1]  412.28 69.11 0 top
C643  0.1UF_16V  [BC0603_P1_1]  412.28 71.04 0 top
C644  0.1UF_16V  [BC0603_P1_1]  412.28 72.97 0 top
C645  0.1UF_16V  [BC0603_P1_1]  412.28 74.9 0 top
C646  0.1UF_16V  [BC0603_P1_1]  412.28 76.83 0 top
C647  0.1UF_16V  [BC0603_P1_1]  412.28 78.77 0 top
C648  0.1UF_16V  [BC0603_P1_1]  412.28 80.7 0 top
C649  0.1UF_16V  [BC0603_P1_1]  412.28 82.63 0 top
C650  0.1UF_16V  [BC0603_P1_1]  412.28 84.56 0 top
C651  0.1UF_16V  [BC0603_P1_1]  412.28 86.49 0 top
C652  0.1UF_16V  [BC0603_P1_1]  412.28 88.42 0 top
C653  0.1UF_16V  [BC0603_P1_1]  412.28 90.35 0 top
C654  0.1UF_16V  [BC0603_P1_1]  412.28 92.28 0 top
C655  0.1UF_16V  [BC0603_P1_1]  412.28 94.21 0 top
C656  0.1UF_16V  [BC0603_P1_1]  412.28 96.14 0 top
C657  0.1UF_16V  [BC0603_P1_1]  412.28 98.07 0 top
C658  0.1UF_16V  [BC0603_P1_1]  412.28 100 0 top
C659  0.1UF_16V  [BC0603_P1_1]  412.28 101.93 0 top
C660  0.1UF_16V  [BC0603_P1_1]  412.28 103.86 0 top
C661  0.1UF_16V  [BC0603_P1_1]  412.28 105.79 0 top
C662  0.1UF_16V  [BC0603_P1_1]  412.28 107.72 0 top
C663  0.1UF_16V  [BC0603_P1_1]  412.28 109.65 0 top
C664  220UF_10V  [7343H_1]  383.1 15.34 0 top
C665  220UF_10V  [7343H_1]  383.1 22.71 0 top
C666  220UF_10V  [7343H_1]  383.1 30.07 0 top
C667  220UF_10V  [7343H_1]  383.1 37.44 0 top
C668  180PF_50V  [RC0603_1]  399.53 6.22 0 top
C669  180PF_50V  [RC0603_1]  399.53 8.15 0 top
C670  180PF_50V  [RC0603_1]  399.53 10.08 0 top
C671  180PF_50V  [RC0603_1]  399.53 12.01 0 top
C672  180PF_50V  [RC0603_1]  399.53 13.94 0 top
C673  180PF_50V  [RC0603_1]  399.53 15.88 0 top
C674  180PF_50V  [RC0603_1]  399.53 17.81 0 top
C675  180PF_50V  [RC0603_1]  399.53 19.74 0 top
C676  10.0UF_16V  [B3528-5X63_1]  405.7 81.1 0 top
C677  10.0UF_16V  [B3528-5X63_1]  405.7 74.5 0 top
C678  10.0UF_16V  [B3528-5X63_1]  405.7 67.89 0 top
C679  10.0UF_16V  [B3528-5X63_1]  405.7 61.29 0 top
C680  10.0UF_16V  [B3528-5X63_1]  405.7 54.69 0 top
C681  10.0UF_16V  [B3528-5X63_1]  405.7 48.08 0 top
C682  10.0UF_16V  [B3528-5X63_1]  405.7 41.48 0 top
C683  10.0UF_16V  [B3528-5X63_1]  405.7 34.87 0 top
C684  180PF_50V  [RC0603_1]  399.53 21.67 0 top
C685  180PF_50V  [RC0603_1]  399.53 23.6 0 top
C686  240PF_50V  [RC0603_1]  369.79 22.48 0 top
C687  240PF_50V  [RC0603_1]  369.79 20.55 0 top
C688  240PF_50V  [RC0603_1]  369.79 18.62 0 top
C689  240PF_50V  [RC0603_1]  369.79 16.69 0 top
C690  240PF_50V  [RC0603_1]  369.79 14.76 0 top
C691  240PF_50V  [RC0603_1]  369.79 12.83 0 top
C692  470PF_50V  [RC0603_1]  379.19 6.83 0 top
C693  470PF_50V  [RC0603_1]  379.19 8.76 0 top
C694  470PF_50V  [RC0603_1]  379.19 10.69 0 top
C695  10.0UF_16V  [B3528-5X63_1]  244.04 -78.83 0 top
C696  10.0UF_16V  [B3528-5X63_1]  373.01 44.42 0 top
C697  10.0UF_16V  [B3528-5X63_1]  393.36 100.41 0 top
C698  10.0UF_16V  [B3528-5X63_1]  405.7 28.27 0 top
C699  0.1UF_16V  [RC0603_1]  198.83 -8.85 0 top
C700  0.1UF_16V  [RC0603_1]  447.59 60.27 0 top
C701  0.1UF_16V  [RC0603_1]  447.59 62.2 0 top
C702  0.1UF_16V  [RC0603_1]  447.59 64.14 0 top
C703  220UF_10V  [7343H_1]  383.1 44.81 0 top
C704  220UF_10V  [7343H_1]  383.1 52.17 0 top
C705  220UF_10V  [7343H_1]  383.1 59.54 0 top
C706  220UF_10V  [7343H_1]  383.1 66.9 0 top
C707  220UF_10V  [7343H_1]  383.1 74.27 0 top
C708  220UF_10V  [7343H_1]  383.1 81.64 0 top
C709  220UF_10V  [7343H_1]  383.1 89 0 top
C710  220UF_10V  [7343H_1]  383.1 96.37 0 top
C711  0.1UF_16V  [BC0603_P1_1]  412.28 111.58 0 top
D1  -  [TO-252AA_1]  360.92 78.65 0 top
D2  -  [TO-252AA_1]  360.92 57.82 0 top
J1  -  [CONM_BGA200_1]  304.82 111.67 0 top
J2  -  [CONM38P_MICTOR_1]  294.76 67.25 0 top
J3  -  [CONM38P_MICTOR_1]  294.76 78.93 0 top
J4  -  [CONM38P_MICTOR_1]  294.76 90.62 0 top
J5  -  [CONM38P_MICTOR_1]  294.76 55.57 0 top
J6  -  [CONM38P_MICTOR_1]  294.76 43.88 0 top
J7  -  [HDR1X2RA_SMT_100_1]  380.89 119.38 0 top
P1  -  [HDR2X6V_100SMT_1]  348.73 121.92 0 top
PS1  -  [VREG_400G_14P_1]  293.11 5.65 0 top
Q1  -  [SOT_23_1]  359.15 65.51 0 top
R1  10.0K  [RC0603_1]  402.48 106.6 0 top
R2  63.4  [RC0603_1]  366.84 21.67 0 top
R3  63.4  [RC0603_1]  366.84 23.6 0 top
R4  63.4  [RC0603_1]  366.84 25.53 0 top
R5  63.4  [RC0603_1]  366.84 27.46 0 top
R6  63.4  [RC0603_1]  366.84 29.39 0 top
R7  63.4  [RC0603_1]  366.84 31.32 0 top
R8  63.4  [RC0603_1]  366.84 33.25 0 top
R9  63.4  [RC0603_1]  369.79 48.69 0 top
R10  63.4  [RC0603_1]  366.84 37.11 0 top
R11  63.4  [RC0603_1]  366.84 39.04 0 top
R12  63.4  [RC0603_1]  366.84 40.97 0 top
R13  63.4  [RC0603_1]  366.84 42.9 0 top
R14  63.4  [RC0603_1]  366.84 44.83 0 top
R15  63.4  [RC0603_1]  379.19 110.67 0 top
R16  63.4  [RC0603_1]  366.84 48.69 0 top
R17  63.4  [RC0603_1]  369.79 1.24 0 top
R18  63.4  [RC0603_1]  369.79 5.11 0 top
R19  63.4  [RC0603_1]  366.84 54.48 0 top
R20  63.4  [RC0603_1]  366.84 56.41 0 top
R21  63.4  [RC0603_1]  366.84 58.34 0 top
R22  63.4  [RC0603_1]  366.84 60.27 0 top
R23  63.4  [RC0603_1]  366.84 62.2 0 top
R24  63.4  [RC0603_1]  366.84 64.14 0 top
R25  63.4  [RC0603_1]  366.84 66.07 0 top
R26  63.4  [RC0603_1]  366.84 68 0 top
R27  63.4  [RC0603_1]  366.84 69.93 0 top
R28  63.4  [RC0603_1]  366.84 71.86 0 top
R29  63.4  [RC0603_1]  366.84 73.79 0 top
R30  63.4  [RC0603_1]  366.84 75.72 0 top
R31  63.4  [RC0603_1]  366.84 77.65 0 top
R32  63.4  [RC0603_1]  366.84 79.58 0 top
R33  63.4  [RC0603_1]  366.84 81.51 0 top
R34  63.4  [RC0603_1]  366.84 83.44 0 top
R35  63.4  [RC0603_1]  366.84 85.37 0 top
R36  63.4  [RC0603_1]  366.84 87.3 0 top
R37  63.4  [RC0603_1]  366.84 89.23 0 top
R38  63.4  [RC0603_1]  366.84 91.16 0 top
R39  63.4  [RC0603_1]  366.84 93.09 0 top
R40  63.4  [RC0603_1]  366.84 95.02 0 top
R41  63.4  [RC0603_1]  366.84 96.95 0 top
R42  63.4  [RC0603_1]  366.84 98.88 0 top
R43  63.4  [RC0603_1]  366.84 35.18 0 top
R44  63.4  [RC0603_1]  366.84 102.74 0 top
R45  63.4  [RC0603_1]  366.84 104.67 0 top
R46  63.4  [RC0603_1]  366.84 106.6 0 top
R47  63.4  [RC0603_1]  366.84 46.76 0 top
R48  63.4  [RC0603_1]  366.84 110.46 0 top
R49  63.4  [RC0603_1]  366.84 112.39 0 top
R50  63.4  [RC0603_1]  366.84 52.55 0 top
R51  63.4  [RC0603_1]  366.84 116.26 0 top
R52  63.4  [RC0603_1]  366.84 100.81 0 top
R53  63.4  [RC0603_1]  366.84 120.12 0 top
R54  63.4  [RC0603_1]  366.84 122.05 0 top
R55  63.4  [RC0603_1]  366.84 123.98 0 top
R56  63.4  [RC0603_1]  366.84 125.91 0 top
R57  63.4  [RC0603_1]  358.46 1.55 0 top
R58  63.4  [RC0603_1]  358.46 3.48 0 top
R59  63.4  [RC0603_1]  358.46 5.41 0 top
R60  63.4  [RC0603_1]  358.46 7.34 0 top
R61  63.4  [RC0603_1]  358.46 9.27 0 top
R62  63.4  [RC0603_1]  358.46 11.2 0 top
R63  63.4  [RC0603_1]  358.46 13.13 0 top
R64  63.4  [RC0603_1]  366.84 108.53 0 top
R65  63.4  [RC0603_1]  358.46 16.99 0 top
R66  63.4  [RC0603_1]  366.84 114.33 0 top
R67  63.4  [RC0603_1]  358.46 20.85 0 top
R68  63.4  [RC0603_1]  366.84 118.19 0 top
R69  63.4  [RC0603_1]  358.46 15.06 0 top
R70  63.4  [RC0603_1]  358.46 26.64 0 top
R71  63.4  [RC0603_1]  358.46 28.57 0 top
R72  63.4  [RC0603_1]  358.46 30.51 0 top
R73  63.4  [RC0603_1]  358.46 32.44 0 top
R74  63.4  [RC0603_1]  358.46 34.37 0 top
R75  63.4  [RC0603_1]  358.46 18.92 0 top
R76  63.4  [RC0603_1]  358.46 22.78 0 top
R77  63.4  [RC0603_1]  358.46 36.3 0 top
R78  63.4  [RC0603_1]  358.46 42.09 0 top
R79  63.4  [RC0603_1]  358.46 44.02 0 top
R80  63.4  [RC0603_1]  358.46 45.95 0 top
R81  1.00K  [RC0603_1]  402.48 98.88 0 top
R82  63.4  [RC0603_1]  358.46 47.88 0 top
R83  63.4  [RC0603_1]  358.46 49.81 0 top
R84  63.4  [RC0603_1]  358.46 40.16 0 top
R85  63.4  [RC0603_1]  358.46 38.23 0 top
R86  10.0K  [RC0603_1]  402.48 108.53 0 top
R87  10.0K  [RC0603_1]  402.48 110.46 0 top
R88  100  [RC0603_1]  369.79 50.62 0 top
R89  100  [RC0603_1]  369.79 52.55 0 top
R90  100  [RC0603_1]  369.79 54.48 0 top
R91  100  [RC0603_1]  369.79 56.41 0 top
R92  100  [RC0603_1]  369.79 58.34 0 top
R93  100  [RC0603_1]  369.79 60.27 0 top
R94  100  [RC0603_1]  369.79 62.2 0 top
R95  100  [RC0603_1]  369.79 64.14 0 top
R96  100  [RC0603_1]  369.79 66.07 0 top
R97  100  [RC0603_1]  369.79 68 0 top
R98  100  [RC0603_1]  369.79 69.93 0 top
R99  100  [RC0603_1]  369.79 71.86 0 top
R100  100  [RC0603_1]  369.79 73.79 0 top
R101  100  [RC0603_1]  369.79 75.72 0 top
R102  100  [RC0603_1]  369.79 77.65 0 top
R103  100  [RC0603_1]  369.79 79.58 0 top
R104  100  [RC0603_1]  369.79 81.51 0 top
R105  100  [RC0603_1]  369.79 83.44 0 top
R106  100  [RC0603_1]  369.79 85.37 0 top
R107  100  [RC0603_1]  369.79 87.3 0 top
R108  100  [RC0603_1]  369.79 89.23 0 top
R109  100  [RC0603_1]  369.79 91.16 0 top
R110  100  [RC0603_1]  369.79 93.09 0 top
R111  100  [RC0603_1]  369.79 95.02 0 top
R112  100  [RC0603_1]  369.79 96.95 0 top
R113  100  [RC0603_1]  369.79 98.88 0 top
R114  100  [RC0603_1]  369.79 100.81 0 top
R115  100  [RC0603_1]  369.79 102.74 0 top
R116  100  [RC0603_1]  369.79 104.67 0 top
R117  100  [RC0603_1]  369.79 106.6 0 top
R118  100  [RC0603_1]  369.79 108.53 0 top
R119  100  [RC0603_1]  369.79 110.46 0 top
R120  100  [RC0603_1]  369.79 112.39 0 top
R121  100  [RC0603_1]  369.79 114.33 0 top
R122  100  [RC0603_1]  369.79 116.26 0 top
R123  100  [RC0603_1]  369.79 118.19 0 top
R124  100  [RC0603_1]  369.79 120.12 0 top
R125  100  [RC0603_1]  369.79 122.05 0 top
R126  100  [RC0603_1]  369.79 123.98 0 top
R127  100  [RC0603_1]  369.79 125.91 0 top
R128  0  [RC0603_1]  411.88 122.05 0 top
R129  0  [RC0603_1]  411.88 123.98 0 top
R130  0  [RC0603_1]  411.88 125.91 0 top
R131  0  [RC0603_1]  402.48 0.84 0 top
R132  0  [RC0603_1]  402.48 2.77 0 top
R133  0  [RC0603_1]  402.48 4.7 0 top
R134  0  [RC0603_1]  402.48 6.63 0 top
R135  0  [RC0603_1]  402.48 8.56 0 top
R136  1.00K  [RC0603_1]  402.48 100.81 0 top
R137  63.4  [RC0603_1]  366.84 2.36 0 top
R138  63.4  [RC0603_1]  366.84 4.29 0 top
R139  63.4  [RC0603_1]  358.46 24.71 0 top
R140  1.00K  [RC0603_1]  402.48 102.74 0 top
R141  1.00K  [RC0603_1]  402.48 104.67 0 top
R142  63.4  [RC0603_1]  366.84 17.81 0 top
R143  63.4  [RC0603_1]  366.84 50.62 0 top
R144  63.4  [RC0603_1]  369.79 40.16 0 top
R145  63.4  [RC0603_1]  369.79 38.23 0 top
R146  1.00K  [RC0603_1]  402.48 18.21 0 top
R147  1.00K  [RC0603_1]  402.48 20.14 0 top
R148  63.4  [RC0603_1]  366.84 6.22 0 top
R149  63.4  [RC0603_1]  366.84 8.15 0 top
R150  63.4  [RC0603_1]  366.84 10.08 0 top
R151  63.4  [RC0603_1]  366.84 12.01 0 top
R152  63.4  [RC0603_1]  366.84 13.94 0 top
R153  63.4  [RC0603_1]  366.84 15.88 0 top
R154  63.4  [RC0603_1]  379.19 101.02 0 top
R155  63.4  [RC0603_1]  366.84 19.74 0 top
R156  0  [RC1206_1]  251.89 -80.4 0 top
R157  0  [RC1206_1]  371.21 32.08 0 top
R158  0  [RC1206_1]  371.21 28.63 0 top
R159  0  [RC1206_1]  371.21 25.17 0 top
R160  33.2  [RC0603_1]  402.48 95.02 0 top
R161  33.2  [RC0603_1]  402.48 93.09 0 top
R162  33.2  [RC0603_1]  402.48 91.16 0 top
R163  33.2  [RC0603_1]  402.48 89.23 0 top
R164  33.2  [RC0603_1]  402.48 87.3 0 top
R165  33.2  [RC0603_1]  402.48 85.37 0 top
R166  10.0K  [RC0603_1]  402.48 112.39 0 top
R167  10.0K  [RC0603_1]  402.48 114.33 0 top
R168  10.0K  [RC0603_1]  402.48 116.26 0 top
R169  10.0K  [RC0603_1]  402.48 118.19 0 top
R170  10.0K  [RC0603_1]  402.48 120.12 0 top
R171  10.0K  [RC0603_1]  402.48 122.05 0 top
R172  10.0K  [RC0603_1]  402.48 123.98 0 top
R173  10.0K  [RC0603_1]  402.48 125.91 0 top
R174  10.0K  [RC0603_1]  399.53 2.36 0 top
R175  10.0K  [RC0603_1]  399.53 4.29 0 top
R176  82.5K  [RC0603_1]  379.19 108.74 0 top
R177  10.0K  [RC0603_1]  369.79 10.9 0 top
R178  10.0K  [RC0603_1]  369.79 8.97 0 top
R179  10.0K  [RC0603_1]  369.79 7.04 0 top
R180  10.0K  [RC0603_1]  369.79 3.17 0 top
R181  10.0K  [RC0603_1]  379.19 102.95 0 top
R182  10.0K  [RC0603_1]  402.48 96.95 0 top
R183  82.5K  [RC0603_1]  379.19 106.81 0 top
R184  82.5K  [RC0603_1]  379.19 104.88 0 top
R185  82.5K  [RC0603_1]  402.48 22.07 0 top
R186  82.5K  [RC0603_1]  402.48 24 0 top
R187  0  [RC0603_1]  402.48 10.49 0 top
R188  0  [RC0603_1]  402.48 12.42 0 top
R189  0  [RC0603_1]  402.48 14.35 0 top
R190  0  [RC0603_1]  402.48 16.28 0 top
RA1  10.0K  [RA0603_4A_1]  342.38 50.8 0 top
RA2  10.0K  [RA0603_4A_1]  342.38 46.23 0 top
RA3  10.0K  [RA0603_4A_1]  342.38 41.66 0 top
RA4  10.0K  [RA0603_4A_1]  342.38 37.08 0 top
RA5  10.0K  [RA0603_4A_1]  342.38 114.81 0 top
RA6  10.0K  [RA0603_4A_1]  342.38 110.24 0 top
RA7  10.0K  [RA0603_4A_1]  342.38 105.66 0 top
RA8  10.0K  [RA0603_4A_1]  342.38 101.09 0 top
RA9  10.0K  [RA0603_4A_1]  342.38 96.52 0 top
RA10  10.0K  [RA0603_4A_1]  342.38 91.95 0 top
RA11  10.0K  [RA0603_4A_1]  342.38 87.38 0 top
RA12  10.0K  [RA0603_4A_1]  342.38 82.8 0 top
RA13  10.0K  [RA0603_4A_1]  342.38 78.23 0 top
RA14  10.0K  [RA0603_4A_1]  342.38 73.66 0 top
RA15  10.0K  [RA0603_4A_1]  342.38 69.09 0 top
RA16  10.0K  [RA0603_4A_1]  342.38 64.52 0 top
RA18  10.0K  [RA0603_4A_1]  342.38 59.94 0 top
RA19  1.0K  [RA0603_4A_1]  342.38 32.51 0 top
RA20  1.0K  [RA0603_4A_1]  342.38 27.94 0 top
RA21  1.0K  [RA0603_4A_1]  256.94 -79.72 0 top
RA22  1.0K  [RA0603_4A_1]  190.58 -29.05 0 top
RA23  10.0K  [RA0603_4A_1]  342.38 55.37 0 top
RA24  1.0K  [RA0603_4A_1]  194.64 -29.05 0 top
RA25  1.0K  [RA0603_4A_1]  342.38 5.08 0 top
RA26  1.0K  [RA0603_4A_1]  358.89 124.71 0 top
RA27  1.0K  [RA0603_4A_1]  342.38 23.37 0 top
RA28  1.0K  [RA0603_4A_1]  358.89 120.14 0 top
RA29  1.0K  [RA0603_4A_1]  358.89 115.57 0 top
RA30  1.0K  [RA0603_4A_1]  358.89 111 0 top
RA31  1.0K  [RA0603_4A_1]  358.89 106.43 0 top
RA32  1.0K  [RA0603_4A_1]  358.89 101.85 0 top
RA33  1.0K  [RA0603_4A_1]  358.89 97.28 0 top
RA34  1.0K  [RA0603_4A_1]  358.89 92.71 0 top
U1  -  [BGA0569_1P27MM_1]  213.88 -56.92 0 top
U2  -  [BGA0569_1P27MM_1]  253.55 101.67 0 top
U3  -  [BGA0569_1P27MM_1]  203.13 51.25 0 top
U4  -  [BGA0569_1P27MM_1]  253.55 51.25 0 top
U5  -  [SOT_23_1]  359.15 69.57 0 top
U6  -  [SOIC8NB_50_1]  361.18 87.3 0 top

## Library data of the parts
C1-C119 C692-C694 = CAPC0034V_V1_R2: tolerance: 5%; room: top_level
C120-C255 = CAPC0004V_V2_R1: tolerance: 10%; room: cam_instance_3
C256-C391 = CAPC0004V_V2_R1: tolerance: 10%; room: cam_instance_4
C392-C527 = CAPC0004V_V2_R1: tolerance: 10%; room: cam_instance_1
C528-C663 = CAPC0004V_V2_R1: tolerance: 10%; room: cam_instance_2
C664-C667 C703-C710 = CAPT0003V_V1_R1: tolerance: 20%; room: top_level
C668-C675 C684 C685 = CAPC0031V_V1_R1: tolerance: 5%; room: top_level
C676-C683 = CAPT0001V_V1_R3: tolerance: 20%; alternate symbols: (3528_1); room: top_level
C686-C691 = CAPC0032V_V1_R1: tolerance: 5%; room: top_level
C695 = CAPT0001V_V1_R3: tolerance: 20%; alternate symbols: (3528_1); room: cam_instance_3
C696 = CAPT0001V_V1_R3: tolerance: 20%; alternate symbols: (3528_1); room: cam_instance_4
C697 = CAPT0001V_V1_R3: tolerance: 20%; alternate symbols: (3528_1); room: cam_instance_1
C698 = CAPT0001V_V1_R3: tolerance: 20%; alternate symbols: (3528_1); room: cam_instance_2
C699 = CAPC0004V_V1_R1: tolerance: 10%; room: cam_instance_3
C700 = CAPC0004V_V1_R1: tolerance: 10%; room: cam_instance_4
C701 = CAPC0004V_V1_R1: tolerance: 10%; room: cam_instance_1
C702 = CAPC0004V_V1_R1: tolerance: 10%; room: cam_instance_2
C711 = CAPC0004V_V2_R1: tolerance: 10%; room: top_level
D1 D2 = DIOD0004V_V1_R1: room: test_power
J1 = CONM0031_V1_R4
J2 J4-J6 = CONM0025_V1_R1: room: test_power
J3 = CONM0025_V1_R1
J7 = PINS0022_V1_R1: room: test_power
P1 = CONM0035_V1_R1: room: test_power
PS1 = PSEM0005_V1_R1: room: test_power
Q1 = XSTR0004_V1_R1: room: top_level
R1 R86 R87 R166-R175 = REST0015H_V1_R1: tolerance: 1%; room: top_level
R2-R80 R82-R85 R137-R139 R142-R145 R148-R155 = REST0018V_V1_R1: tolerance: 1%; room: top_level
R81 R136 R140 R141 = REST0010H_V1_R1: tolerance: 1%; room: top_level
R88-R127 = REST0004V_V1_R1: tolerance: 1%; room: top_level
R128-R135 R187-R190 = REST0017H_V1_R1: tolerance: JUMPER; room: top_level
R146 R147 = REST0010V_V1_R1: tolerance: 1%; room: top_level
R156 = REST0019H_V1_R1: tolerance: JUMPER; room: cam_instance_3
R157 = REST0019H_V1_R1: tolerance: JUMPER; room: cam_instance_4
R158 = REST0019H_V1_R1: tolerance: JUMPER; room: cam_instance_1
R159 = REST0019H_V1_R1: tolerance: JUMPER; room: cam_instance_2
R160-R165 = REST0034H_V1_R1: tolerance: 1%; room: top_level
R176 R183-R186 = REST0046H_V1_R1: tolerance: 1%; room: top_level
R177-R182 = REST0015V_V1_R1: tolerance: 1%; room: top_level
RA1-RA16 RA18 RA23 = RESA0017H_V1_R1: tolerance: 5%; room: top_level
RA19 RA20 RA27 = RESA0016H_V1_R1: tolerance: 5%; room: top_level
RA21 RA22 RA24 = RESA0016H_V1_R1: tolerance: 5%; room: cam_instance_3
RA25 RA26 RA28 = RESA0016H_V1_R1: tolerance: 5%; room: cam_instance_4
RA29-RA31 = RESA0016H_V1_R1: tolerance: 5%; room: cam_instance_1
RA32-RA34 = RESA0016H_V1_R1: tolerance: 5%; room: cam_instance_2
U1 = MEMC0001_V2_R1: room: cam_instance_3
U2 = MEMC0001_V2_R1: room: cam_instance_4
U3 = MEMC0001_V2_R1: room: cam_instance_1
U4 = MEMC0001_V2_R1: room: cam_instance_2
U5 = IC000077_V1_R1: room: top_level
U6 = EPRM0001_V1_R2: room: top_level

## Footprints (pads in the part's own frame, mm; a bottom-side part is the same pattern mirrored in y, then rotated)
7343H_1
  rect 2.54x2.54 smd: 1(-3.429,0) 2(3.429,0)
B3528-5X63_1
  custom 0.584x0.584 smd: 1(-1.727,0) 2(1.727,0)
BC0603_P1_1
  rect 0.889x0.889 smd: 1(-0.813,0) 2(0.813,0)
BGA0569_1P27MM_1
  round 0.66 smd: A1(-19.05,-19.05) A2(-19.05,-17.78) A3(-19.05,-16.51) A4(-19.05,-15.24) A5(-19.05,-13.97) A6(-19.05,-12.7) A7(-19.05,-11.43) A8(-19.05,-10.16) A9(-19.05,-8.89) A10(-19.05,-7.62) A11(-19.05,-6.35) A12(-19.05,-5.08) A13(-19.05,-3.81) A14(-19.05,-2.54) A15(-19.05,-1.27) A16(-19.05,0) A17(-19.05,1.27) A18(-19.05,2.54) A19(-19.05,3.81) A20(-19.05,5.08) A21(-19.05,6.35) A22(-19.05,7.62) A23(-19.05,8.89) A24(-19.05,10.16) A25(-19.05,11.43) A26(-19.05,12.7) A27(-19.05,13.97) A28(-19.05,15.24) A29(-19.05,16.51) A30(-19.05,17.78) A31(-19.05,19.05) AA1(6.35,-19.05) AA2(6.35,-17.78) AA3(6.35,-16.51) AA4(6.35,-15.24) AA5(6.35,-13.97) AA27(6.35,13.97) AA28(6.35,15.24) AA29(6.35,16.51) AA30(6.35,17.78) AA31(6.35,19.05) AB1(7.62,-19.05) AB2(7.62,-17.78) AB3(7.62,-16.51) AB4(7.62,-15.24) AB5(7.62,-13.97) AB27(7.62,13.97) AB28(7.62,15.24) AB29(7.62,16.51) AB30(7.62,17.78) AB31(7.62,19.05) AC1(8.89,-19.05) AC2(8.89,-17.78) AC3(8.89,-16.51) AC4(8.89,-15.24) AC5(8.89,-13.97) AC27(8.89,13.97) AC28(8.89,15.24) AC29(8.89,16.51) AC30(8.89,17.78) AC31(8.89,19.05) AD1(10.16,-19.05) AD2(10.16,-17.78) AD3(10.16,-16.51) AD4(10.16,-15.24) AD5(10.16,-13.97) AD27(10.16,13.97) AD28(10.16,15.24) AD29(10.16,16.51) AD30(10.16,17.78) AD31(10.16,19.05) AE1(11.43,-19.05) AE2(11.43,-17.78) AE3(11.43,-16.51) AE4(11.43,-15.24) AE5(11.43,-13.97) AE27(11.43,13.97) AE28(11.43,15.24) AE29(11.43,16.51) AE30(11.43,17.78) AE31(11.43,19.05) AF1(12.7,-19.05) AF2(12.7,-17.78) AF3(12.7,-16.51) AF4(12.7,-15.24) AF5(12.7,-13.97) AF27(12.7,13.97) AF28(12.7,15.24) AF29(12.7,16.51) AF30(12.7,17.78) AF31(12.7,19.05) AG1(13.97,-19.05) AG2(13.97,-17.78) AG3(13.97,-16.51) AG4(13.97,-15.24) AG5(13.97,-13.97) AG6(13.97,-12.7) AG7(13.97,-11.43) AG8(13.97,-10.16) AG9(13.97,-8.89) AG10(13.97,-7.62) AG11(13.97,-6.35) AG12(13.97,-5.08) AG13(13.97,-3.81) AG14(13.97,-2.54) AG15(13.97,-1.27) AG16(13.97,0) AG17(13.97,1.27) AG18(13.97,2.54) AG19(13.97,3.81) AG20(13.97,5.08) AG21(13.97,6.35) AG22(13.97,7.62) AG23(13.97,8.89) AG24(13.97,10.16) AG25(13.97,11.43) AG26(13.97,12.7) AG27(13.97,13.97) AG28(13.97,15.24) AG29(13.97,16.51) AG30(13.97,17.78) AG31(13.97,19.05) AH1(15.24,-19.05) AH2(15.24,-17.78) AH3(15.24,-16.51) AH4(15.24,-15.24) AH5(15.24,-13.97) AH6(15.24,-12.7) AH7(15.24,-11.43) AH8(15.24,-10.16) AH9(15.24,-8.89) AH10(15.24,-7.62) AH11(15.24,-6.35) AH12(15.24,-5.08) AH13(15.24,-3.81) AH14(15.24,-2.54) AH15(15.24,-1.27) AH16(15.24,0) AH17(15.24,1.27) AH18(15.24,2.54) AH19(15.24,3.81) AH20(15.24,5.08) AH21(15.24,6.35) AH22(15.24,7.62) AH23(15.24,8.89) AH24(15.24,10.16) AH25(15.24,11.43) AH26(15.24,12.7) AH27(15.24,13.97) AH28(15.24,15.24) AH29(15.24,16.51) AH30(15.24,17.78) AH31(15.24,19.05) AJ1(16.51,-19.05) AJ2(16.51,-17.78) AJ3(16.51,-16.51) AJ4(16.51,-15.24) AJ5(16.51,-13.97) AJ6(16.51,-12.7) AJ7(16.51,-11.43) AJ8(16.51,-10.16) AJ9(16.51,-8.89) AJ10(16.51,-7.62) AJ11(16.51,-6.35) AJ12(16.51,-5.08) AJ13(16.51,-3.81) AJ14(16.51,-2.54) AJ15(16.51,-1.27) AJ16(16.51,0) AJ17(16.51,1.27) AJ18(16.51,2.54) AJ19(16.51,3.81) AJ20(16.51,5.08) AJ21(16.51,6.35) AJ22(16.51,7.62) AJ23(16.51,8.89) AJ24(16.51,10.16) AJ25(16.51,11.43) AJ26(16.51,12.7) AJ27(16.51,13.97) AJ28(16.51,15.24) AJ29(16.51,16.51) AJ30(16.51,17.78) AJ31(16.51,19.05) AK1(17.78,-19.05) AK2(17.78,-17.78) AK3(17.78,-16.51) AK4(17.78,-15.24) AK5(17.78,-13.97) AK6(17.78,-12.7) AK7(17.78,-11.43) AK8(17.78,-10.16) AK9(17.78,-8.89) AK10(17.78,-7.62) AK11(17.78,-6.35) AK12(17.78,-5.08) AK13(17.78,-3.81) AK14(17.78,-2.54) AK15(17.78,-1.27) AK16(17.78,0) AK17(17.78,1.27) AK18(17.78,2.54) AK19(17.78,3.81) AK20(17.78,5.08) AK21(17.78,6.35) AK22(17.78,7.62) AK23(17.78,8.89) AK24(17.78,10.16) AK25(17.78,11.43) AK26(17.78,12.7) AK27(17.78,13.97) AK28(17.78,15.24) AK29(17.78,16.51) AK30(17.78,17.78) AK31(17.78,19.05) AL1(19.05,-19.05) AL2(19.05,-17.78) AL3(19.05,-16.51) AL4(19.05,-15.24) AL5(19.05,-13.97) AL6(19.05,-12.7) AL7(19.05,-11.43) AL8(19.05,-10.16) AL9(19.05,-8.89) AL10(19.05,-7.62) AL11(19.05,-6.35) AL12(19.05,-5.08) AL13(19.05,-3.81) AL14(19.05,-2.54) AL15(19.05,-1.27) AL16(19.05,0) AL17(19.05,1.27) AL18(19.05,2.54) AL19(19.05,3.81) AL20(19.05,5.08) AL21(19.05,6.35) AL22(19.05,7.62) AL23(19.05,8.89) AL24(19.05,10.16) AL25(19.05,11.43) AL26(19.05,12.7) AL27(19.05,13.97) AL28(19.05,15.24) AL29(19.05,16.51) AL30(19.05,17.78) AL31(19.05,19.05) B1(-17.78,-19.05) B2(-17.78,-17.78) B3(-17.78,-16.51) B4(-17.78,-15.24) B5(-17.78,-13.97) B6(-17.78,-12.7) B7(-17.78,-11.43) B8(-17.78,-10.16) B9(-17.78,-8.89) B10(-17.78,-7.62) B11(-17.78,-6.35) B12(-17.78,-5.08) B13(-17.78,-3.81) B14(-17.78,-2.54) B15(-17.78,-1.27) B16(-17.78,0) B17(-17.78,1.27) B18(-17.78,2.54) B19(-17.78,3.81) B20(-17.78,5.08) B21(-17.78,6.35) B22(-17.78,7.62) B23(-17.78,8.89) B24(-17.78,10.16) B25(-17.78,11.43) B26(-17.78,12.7) B27(-17.78,13.97) B28(-17.78,15.24) B29(-17.78,16.51) B30(-17.78,17.78) B31(-17.78,19.05) C1(-16.51,-19.05) C2(-16.51,-17.78) C3(-16.51,-16.51) C4(-16.51,-15.24) C5(-16.51,-13.97) C6(-16.51,-12.7) C7(-16.51,-11.43) C8(-16.51,-10.16) C9(-16.51,-8.89) C10(-16.51,-7.62) C11(-16.51,-6.35) C12(-16.51,-5.08) C13(-16.51,-3.81) C14(-16.51,-2.54) C15(-16.51,-1.27) C16(-16.51,0) C17(-16.51,1.27) C18(-16.51,2.54) C19(-16.51,3.81) C20(-16.51,5.08) C21(-16.51,6.35) C22(-16.51,7.62) C23(-16.51,8.89) C24(-16.51,10.16) C25(-16.51,11.43) C26(-16.51,12.7) C27(-16.51,13.97) C28(-16.51,15.24) C29(-16.51,16.51) C30(-16.51,17.78) C31(-16.51,19.05) D1(-15.24,-19.05) D2(-15.24,-17.78) D3(-15.24,-16.51) D4(-15.24,-15.24) D5(-15.24,-13.97) D6(-15.24,-12.7) D7(-15.24,-11.43) D8(-15.24,-10.16) D9(-15.24,-8.89) D10(-15.24,-7.62) D11(-15.24,-6.35) D12(-15.24,-5.08) D13(-15.24,-3.81) D14(-15.24,-2.54) D15(-15.24,-1.27) D16(-15.24,0) D17(-15.24,1.27) D18(-15.24,2.54) D19(-15.24,3.81) D20(-15.24,5.08) D21(-15.24,6.35) D22(-15.24,7.62) D23(-15.24,8.89) D24(-15.24,10.16) D25(-15.24,11.43) D26(-15.24,12.7) D27(-15.24,13.97) D28(-15.24,15.24) D29(-15.24,16.51) D30(-15.24,17.78) D31(-15.24,19.05) E1(-13.97,-19.05) E2(-13.97,-17.78) E3(-13.97,-16.51) E4(-13.97,-15.24) E5(-13.97,-13.97) E6(-13.97,-12.7) E7(-13.97,-11.43) E8(-13.97,-10.16) E9(-13.97,-8.89) E10(-13.97,-7.62) E11(-13.97,-6.35) E12(-13.97,-5.08) E13(-13.97,-3.81) E14(-13.97,-2.54) E15(-13.97,-1.27) E16(-13.97,0) E17(-13.97,1.27) E18(-13.97,2.54) E19(-13.97,3.81) E20(-13.97,5.08) E21(-13.97,6.35) E22(-13.97,7.62) E23(-13.97,8.89) E24(-13.97,10.16) E25(-13.97,11.43) E26(-13.97,12.7) E27(-13.97,13.97) E28(-13.97,15.24) E29(-13.97,16.51) E30(-13.97,17.78) E31(-13.97,19.05) F1(-12.7,-19.05) F2(-12.7,-17.78) F3(-12.7,-16.51) F4(-12.7,-15.24) F5(-12.7,-13.97) F27(-12.7,13.97) F28(-12.7,15.24) F29(-12.7,16.51) F30(-12.7,17.78) F31(-12.7,19.05) G1(-11.43,-19.05) G2(-11.43,-17.78) G3(-11.43,-16.51) G4(-11.43,-15.24) G5(-11.43,-13.97) G27(-11.43,13.97) G28(-11.43,15.24) G29(-11.43,16.51) G30(-11.43,17.78) G31(-11.43,19.05) H1(-10.16,-19.05) H2(-10.16,-17.78) H3(-10.16,-16.51) H4(-10.16,-15.24) H5(-10.16,-13.97) H27(-10.16,13.97) H28(-10.16,15.24) H29(-10.16,16.51) H30(-10.16,17.78) H31(-10.16,19.05) J1(-8.89,-19.05) J2(-8.89,-17.78) J3(-8.89,-16.51) J4(-8.89,-15.24) J5(-8.89,-13.97) J27(-8.89,13.97) J28(-8.89,15.24) J29(-8.89,16.51) J30(-8.89,17.78) J31(-8.89,19.05) K1(-7.62,-19.05) K2(-7.62,-17.78) K3(-7.62,-16.51) K4(-7.62,-15.24) K5(-7.62,-13.97) K27(-7.62,13.97) K28(-7.62,15.24) K29(-7.62,16.51) K30(-7.62,17.78) K31(-7.62,19.05) L1(-6.35,-19.05) L2(-6.35,-17.78) L3(-6.35,-16.51) L4(-6.35,-15.24) L5(-6.35,-13.97) L27(-6.35,13.97) L28(-6.35,15.24) L29(-6.35,16.51) L30(-6.35,17.78) L31(-6.35,19.05) M1(-5.08,-19.05) M2(-5.08,-17.78) M3(-5.08,-16.51) M4(-5.08,-15.24) M5(-5.08,-13.97) M27(-5.08,13.97) M28(-5.08,15.24) M29(-5.08,16.51) M30(-5.08,17.78) M31(-5.08,19.05) N1(-3.81,-19.05) N2(-3.81,-17.78) N3(-3.81,-16.51) N4(-3.81,-15.24) N5(-3.81,-13.97) N13(-3.81,-3.81) N14(-3.81,-2.54) N15(-3.81,-1.27) N16(-3.81,0) N17(-3.81,1.27) N18(-3.81,2.54) N19(-3.81,3.81) N27(-3.81,13.97) N28(-3.81,15.24) N29(-3.81,16.51) N30(-3.81,17.78) N31(-3.81,19.05) P1(-2.54,-19.05) P2(-2.54,-17.78) P3(-2.54,-16.51) P4(-2.54,-15.24) P5(-2.54,-13.97) P13(-2.54,-3.81) P14(-2.54,-2.54) P15(-2.54,-1.27) P16(-2.54,0) P17(-2.54,1.27) P18(-2.54,2.54) P19(-2.54,3.81) P27(-2.54,13.97) P28(-2.54,15.24) P29(-2.54,16.51) P30(-2.54,17.78) P31(-2.54,19.05) R1(-1.27,-19.05) R2(-1.27,-17.78) R3(-1.27,-16.51) R4(-1.27,-15.24) R5(-1.27,-13.97) R13(-1.27,-3.81) R14(-1.27,-2.54) R15(-1.27,-1.27) R16(-1.27,0) R17(-1.27,1.27) R18(-1.27,2.54) R19(-1.27,3.81) R27(-1.27,13.97) R28(-1.27,15.24) R29(-1.27,16.51) R30(-1.27,17.78) R31(-1.27,19.05) T1(0,-19.05) T2(0,-17.78) T3(0,-16.51) T4(0,-15.24) T5(0,-13.97) T13(0,-3.81) T14(0,-2.54) T15(0,-1.27) T16(0,0) T17(0,1.27) T18(0,2.54) T19(0,3.81) T27(0,13.97) T28(0,15.24) T29(0,16.51) T30(0,17.78) T31(0,19.05) U1(1.27,-19.05) U2(1.27,-17.78) U3(1.27,-16.51) U4(1.27,-15.24) U5(1.27,-13.97) U13(1.27,-3.81) U14(1.27,-2.54) U15(1.27,-1.27) U16(1.27,0) U17(1.27,1.27) U18(1.27,2.54) U19(1.27,3.81) U27(1.27,13.97) U28(1.27,15.24) U29(1.27,16.51) U30(1.27,17.78) U31(1.27,19.05) V1(2.54,-19.05) V2(2.54,-17.78) V3(2.54,-16.51) V4(2.54,-15.24) V5(2.54,-13.97) V13(2.54,-3.81) V14(2.54,-2.54) V15(2.54,-1.27) V16(2.54,0) V17(2.54,1.27) V18(2.54,2.54) V19(2.54,3.81) V27(2.54,13.97) V28(2.54,15.24) V29(2.54,16.51) V30(2.54,17.78) V31(2.54,19.05) W1(3.81,-19.05) W2(3.81,-17.78) W3(3.81,-16.51) W4(3.81,-15.24) W5(3.81,-13.97) W13(3.81,-3.81) W14(3.81,-2.54) W15(3.81,-1.27) W16(3.81,0) W17(3.81,1.27) W18(3.81,2.54) W19(3.81,3.81) W27(3.81,13.97) W28(3.81,15.24) W29(3.81,16.51) W30(3.81,17.78) W31(3.81,19.05) Y1(5.08,-19.05) Y2(5.08,-17.78) Y3(5.08,-16.51) Y4(5.08,-15.24) Y5(5.08,-13.97) Y27(5.08,13.97) Y28(5.08,15.24) Y29(5.08,16.51) Y30(5.08,17.78) Y31(5.08,19.05)
